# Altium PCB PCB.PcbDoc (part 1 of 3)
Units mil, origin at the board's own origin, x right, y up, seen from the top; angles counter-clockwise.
Board outline 5000 x 3500 mil, 8 copper layers (Top Layer, L2, L3, L4, L5, L6, L7, Bottom Layer), stack 46.9 mil thick; 123 components, 45 nets, 510 pads, 1300 vias.
Unrouted connection lines stored in the file: 12.
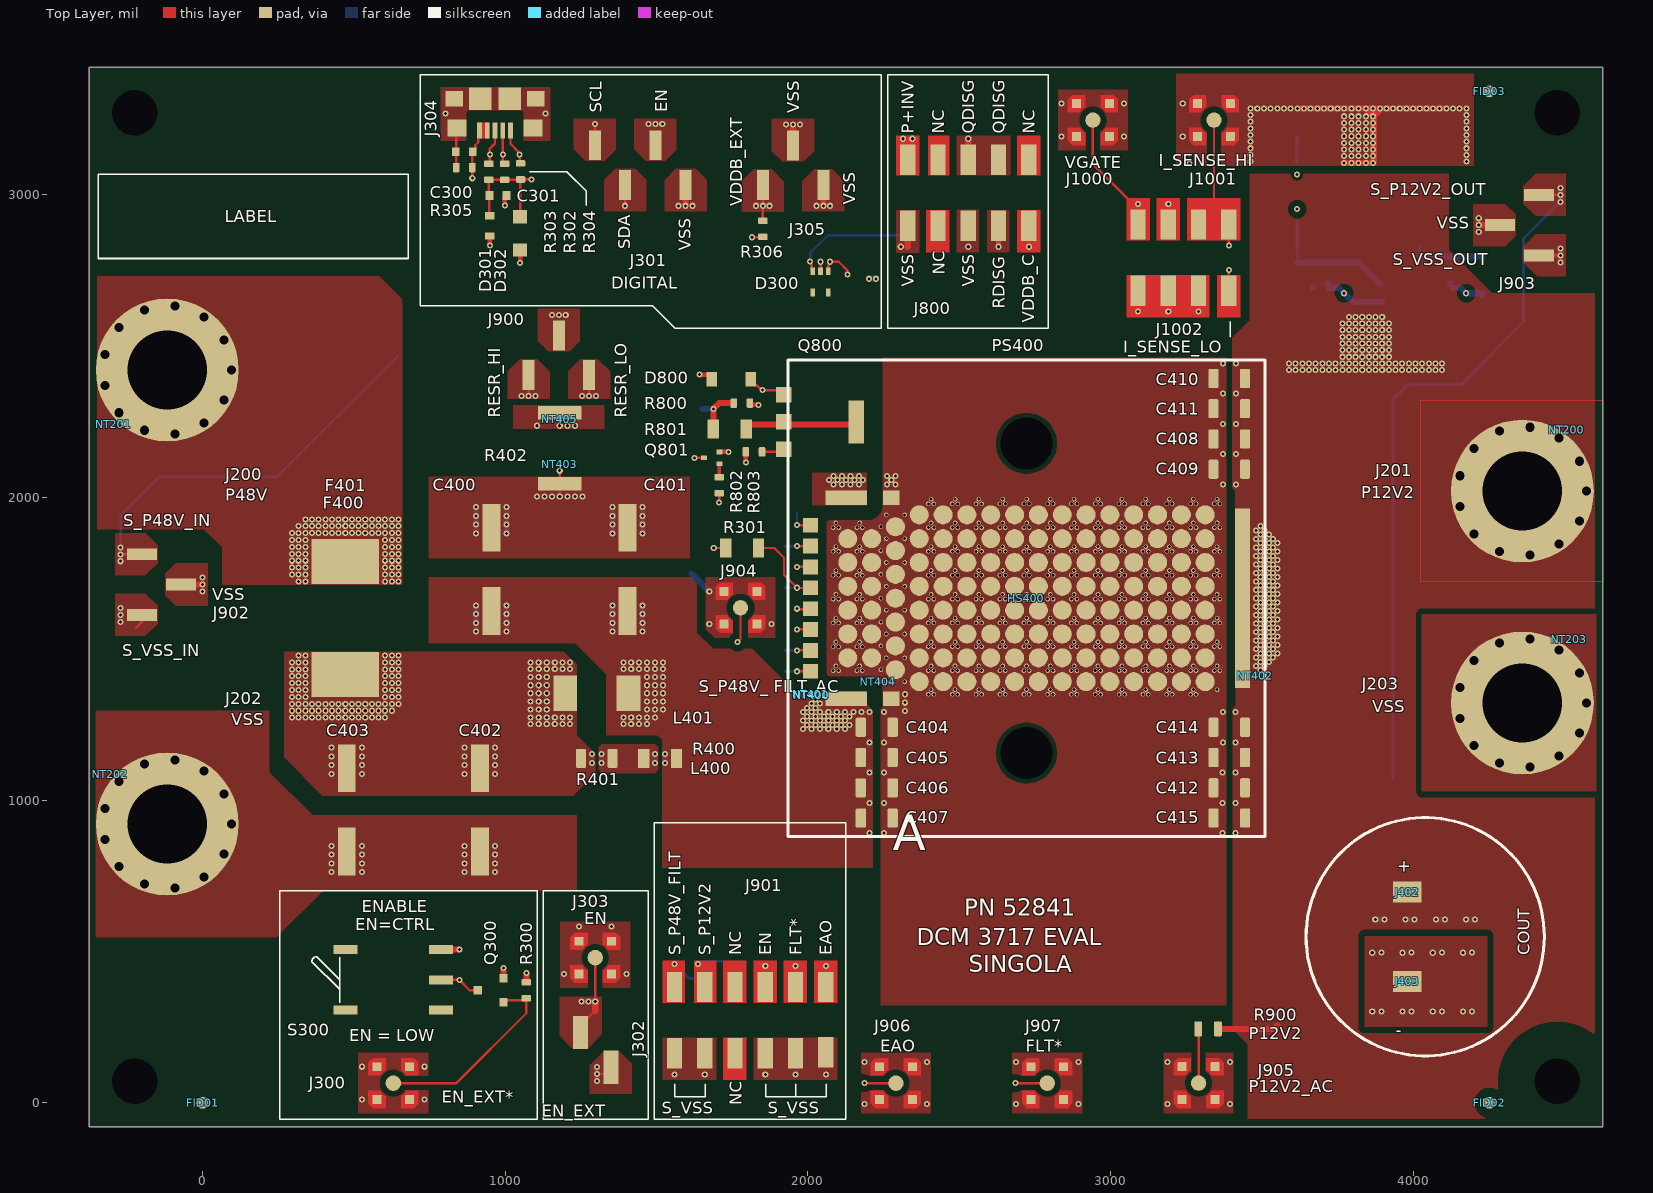
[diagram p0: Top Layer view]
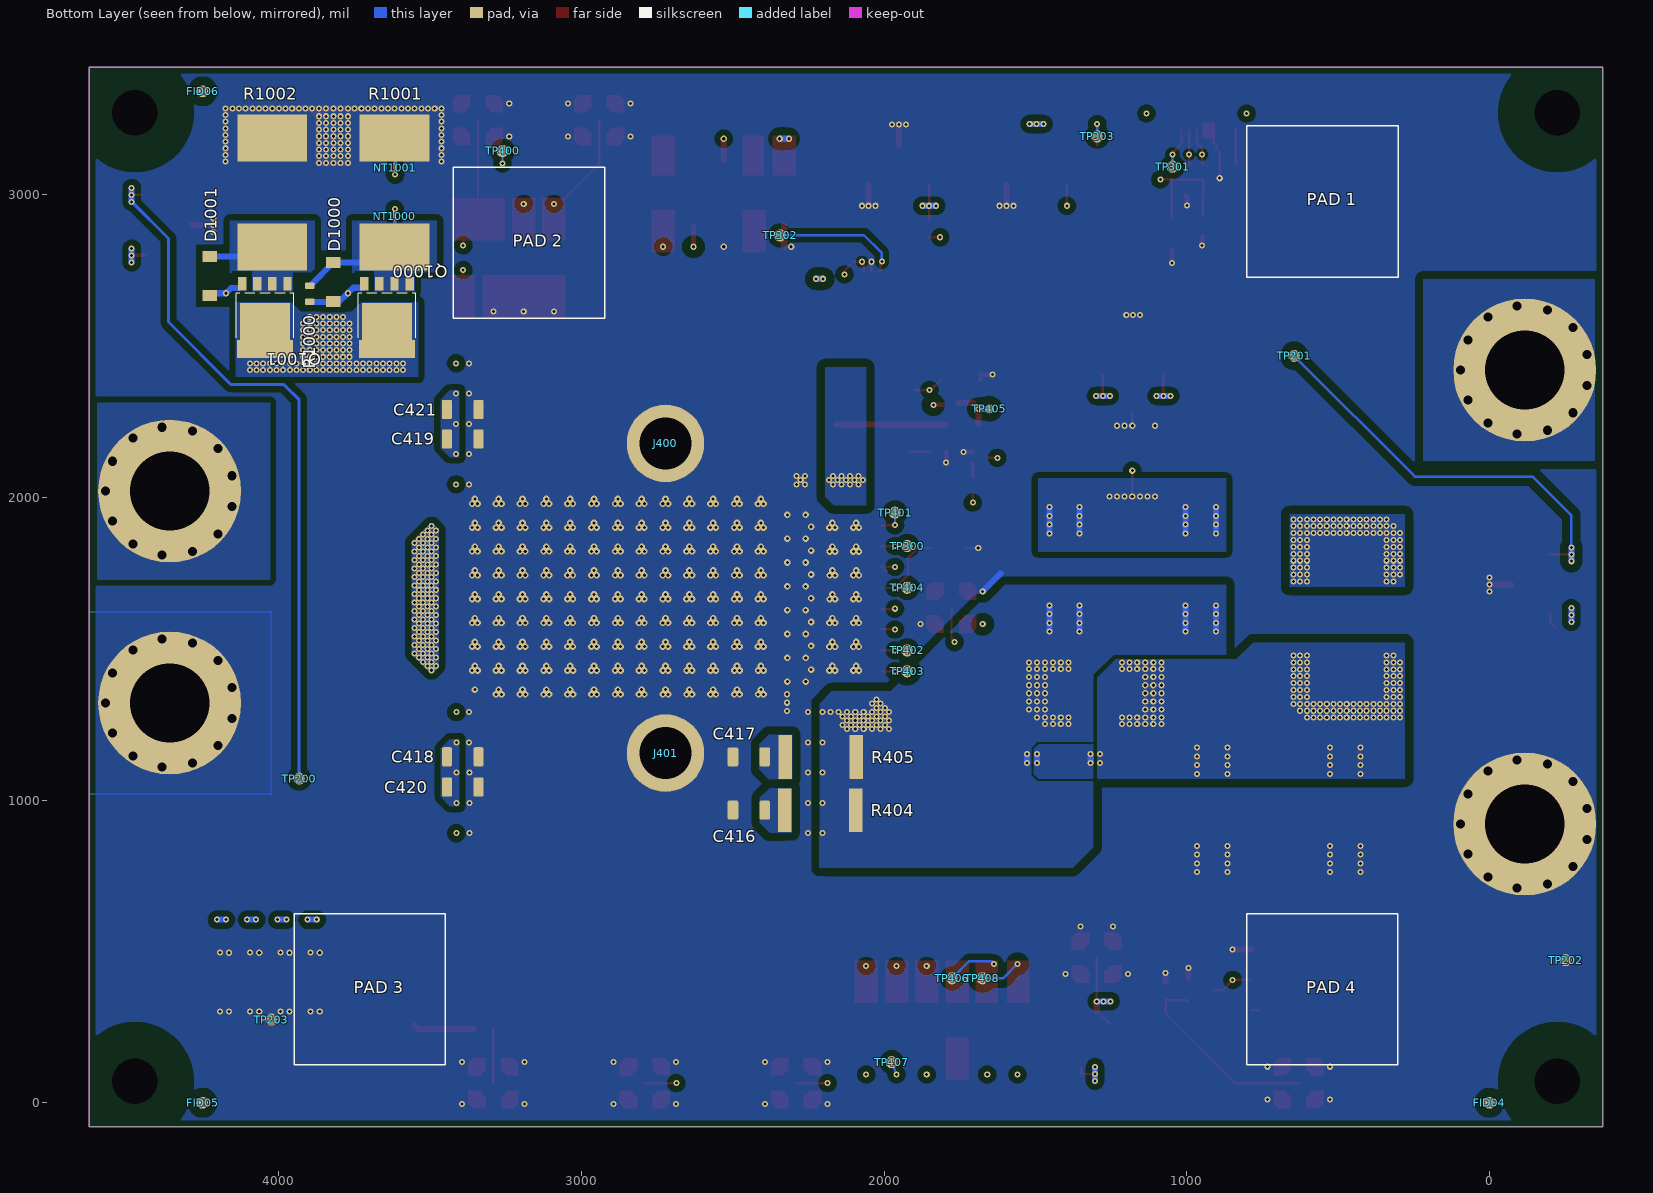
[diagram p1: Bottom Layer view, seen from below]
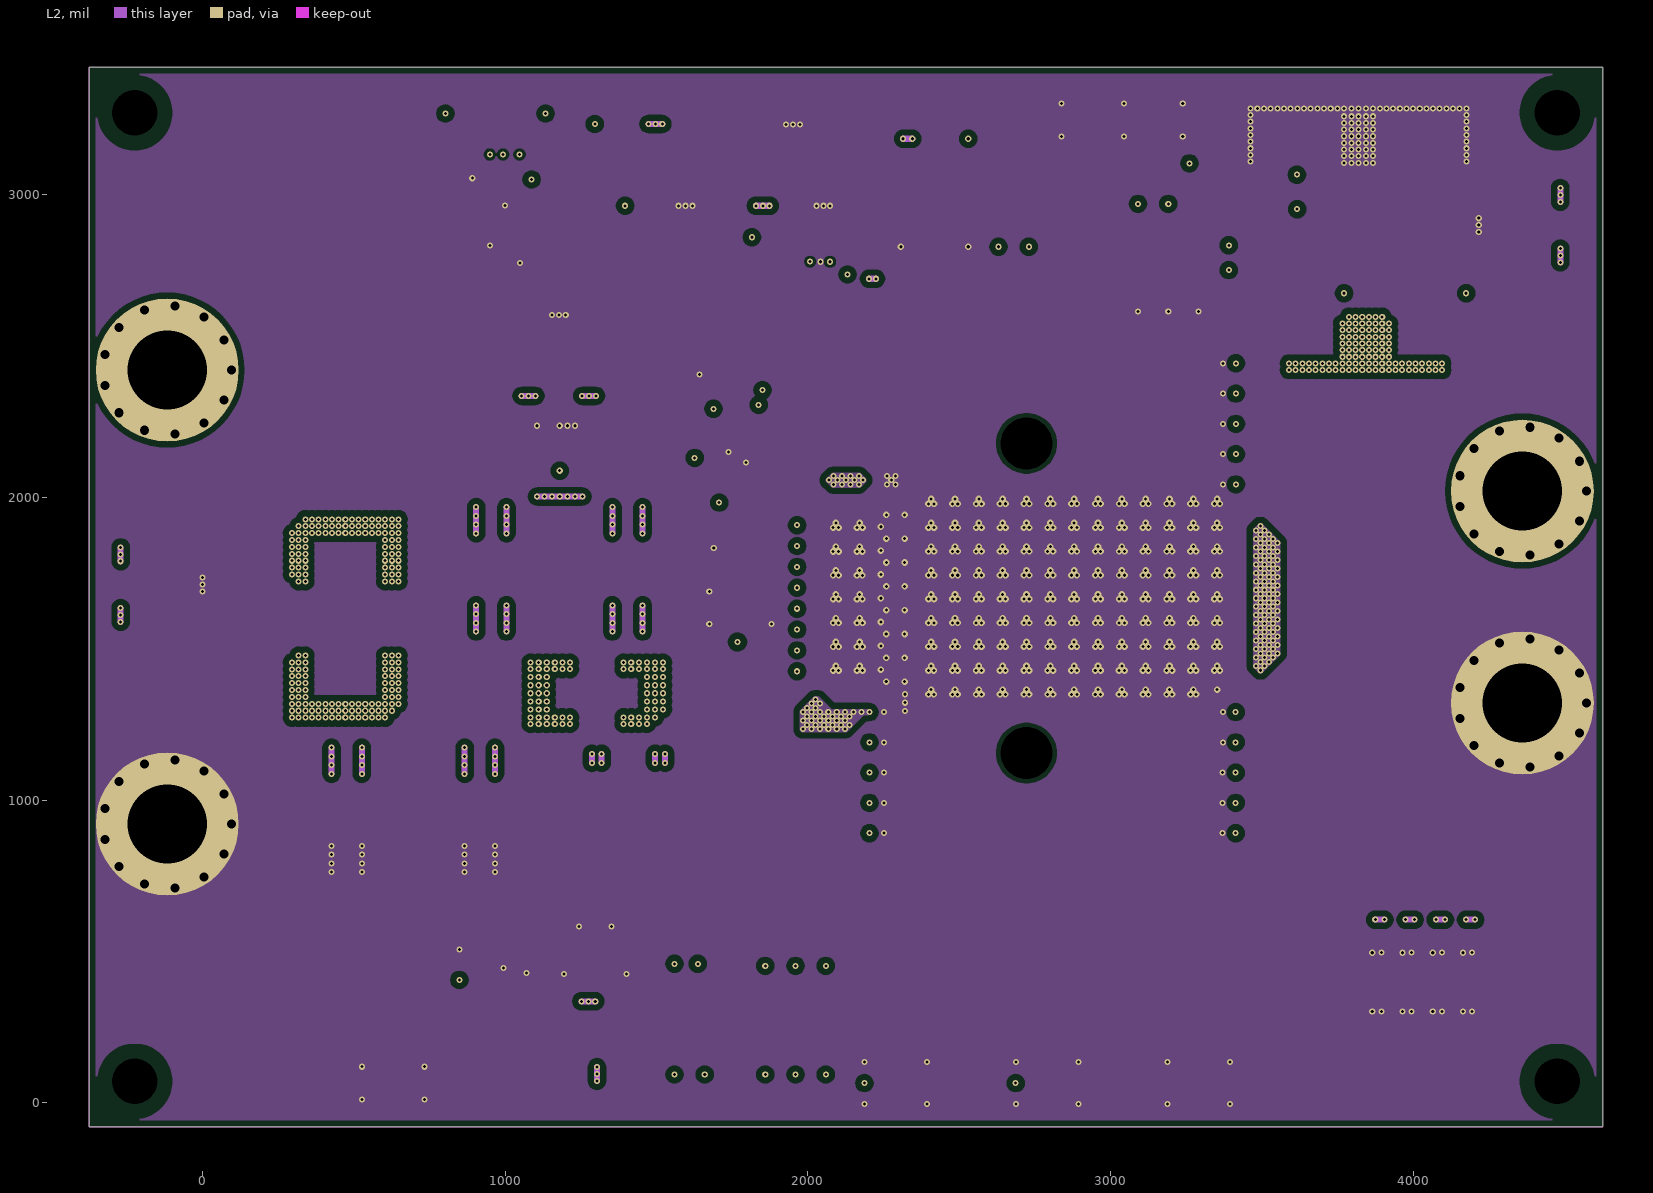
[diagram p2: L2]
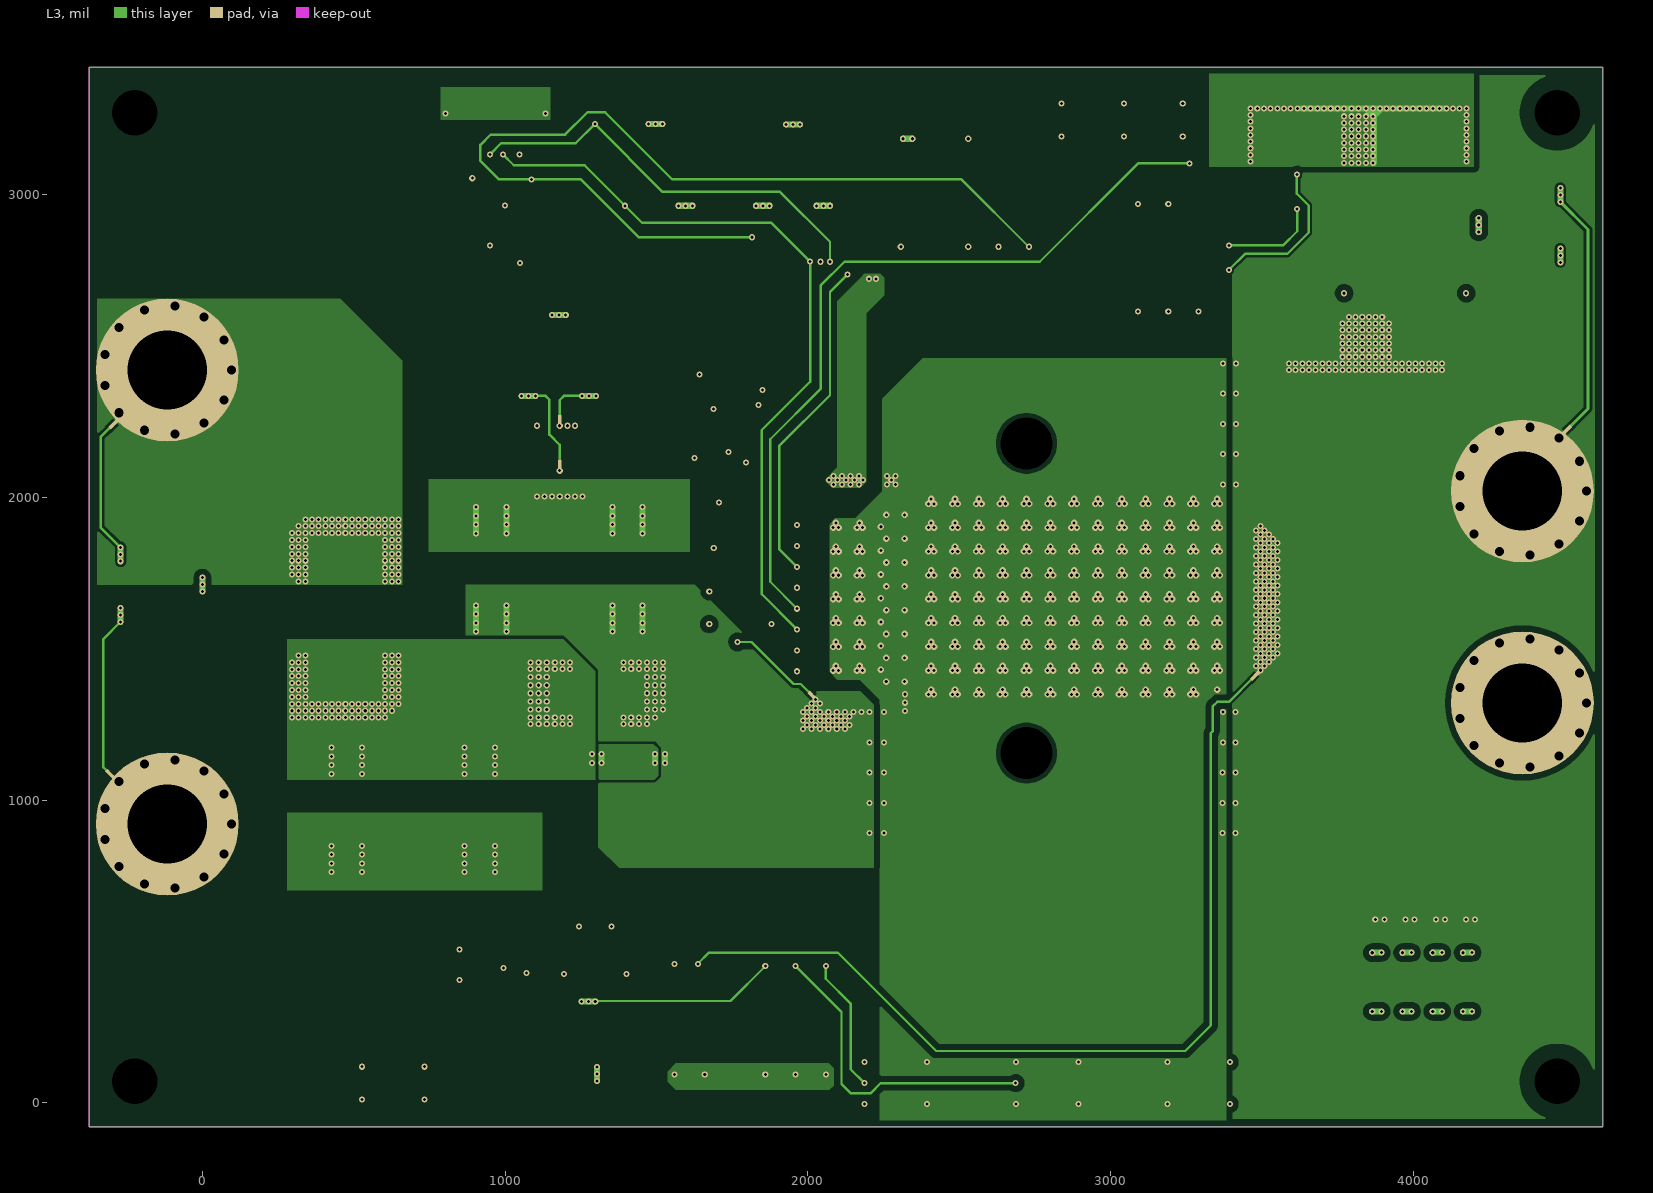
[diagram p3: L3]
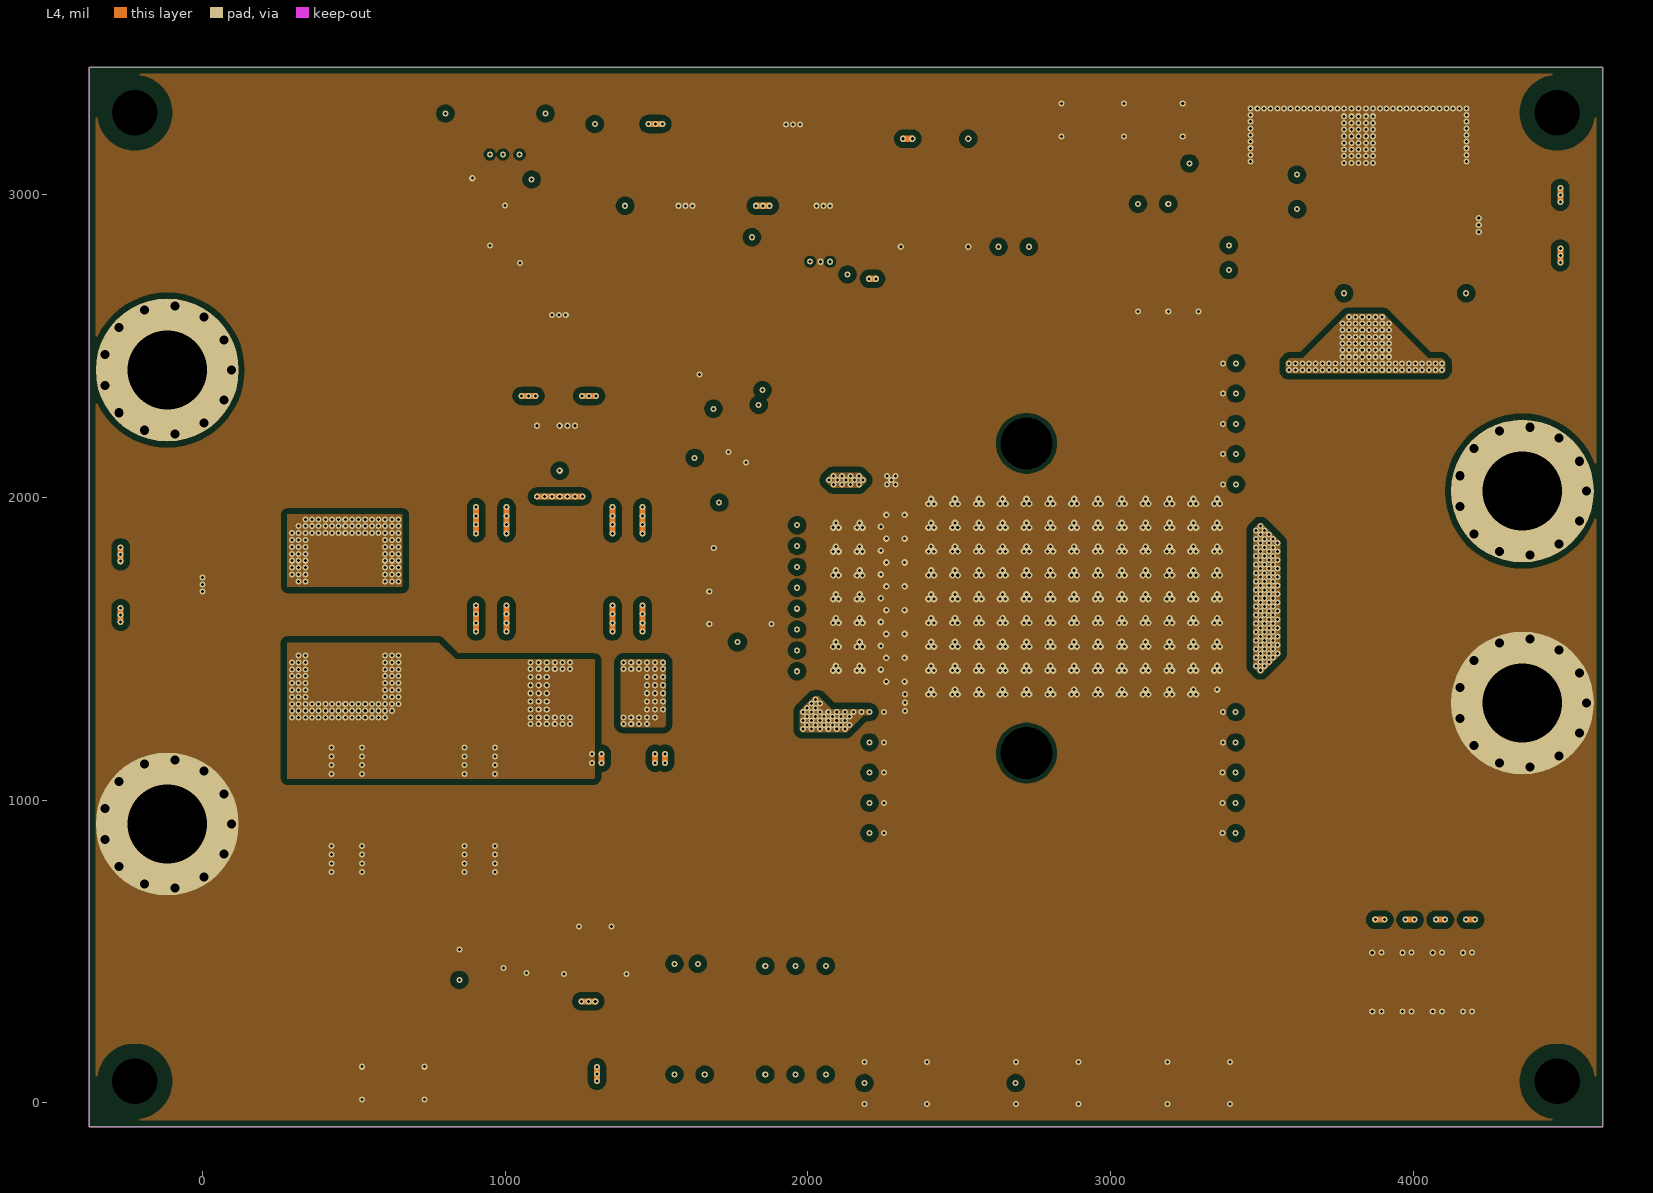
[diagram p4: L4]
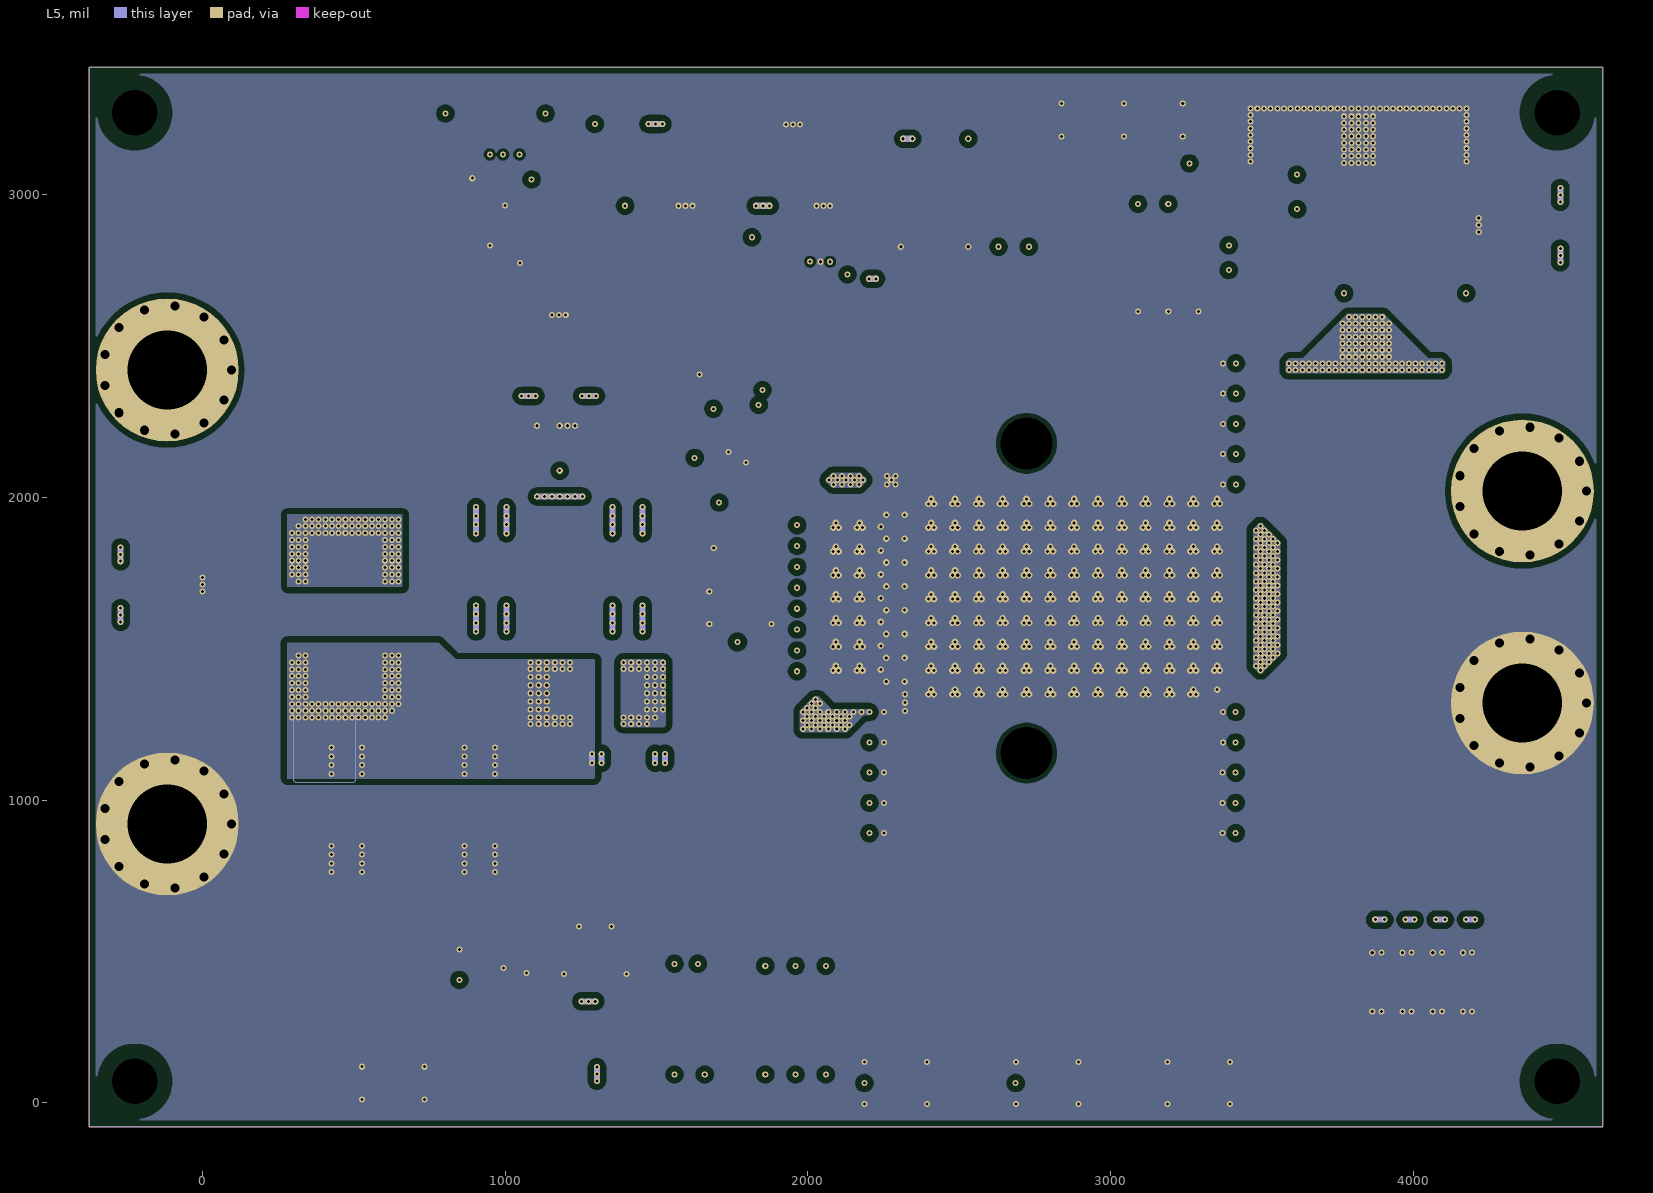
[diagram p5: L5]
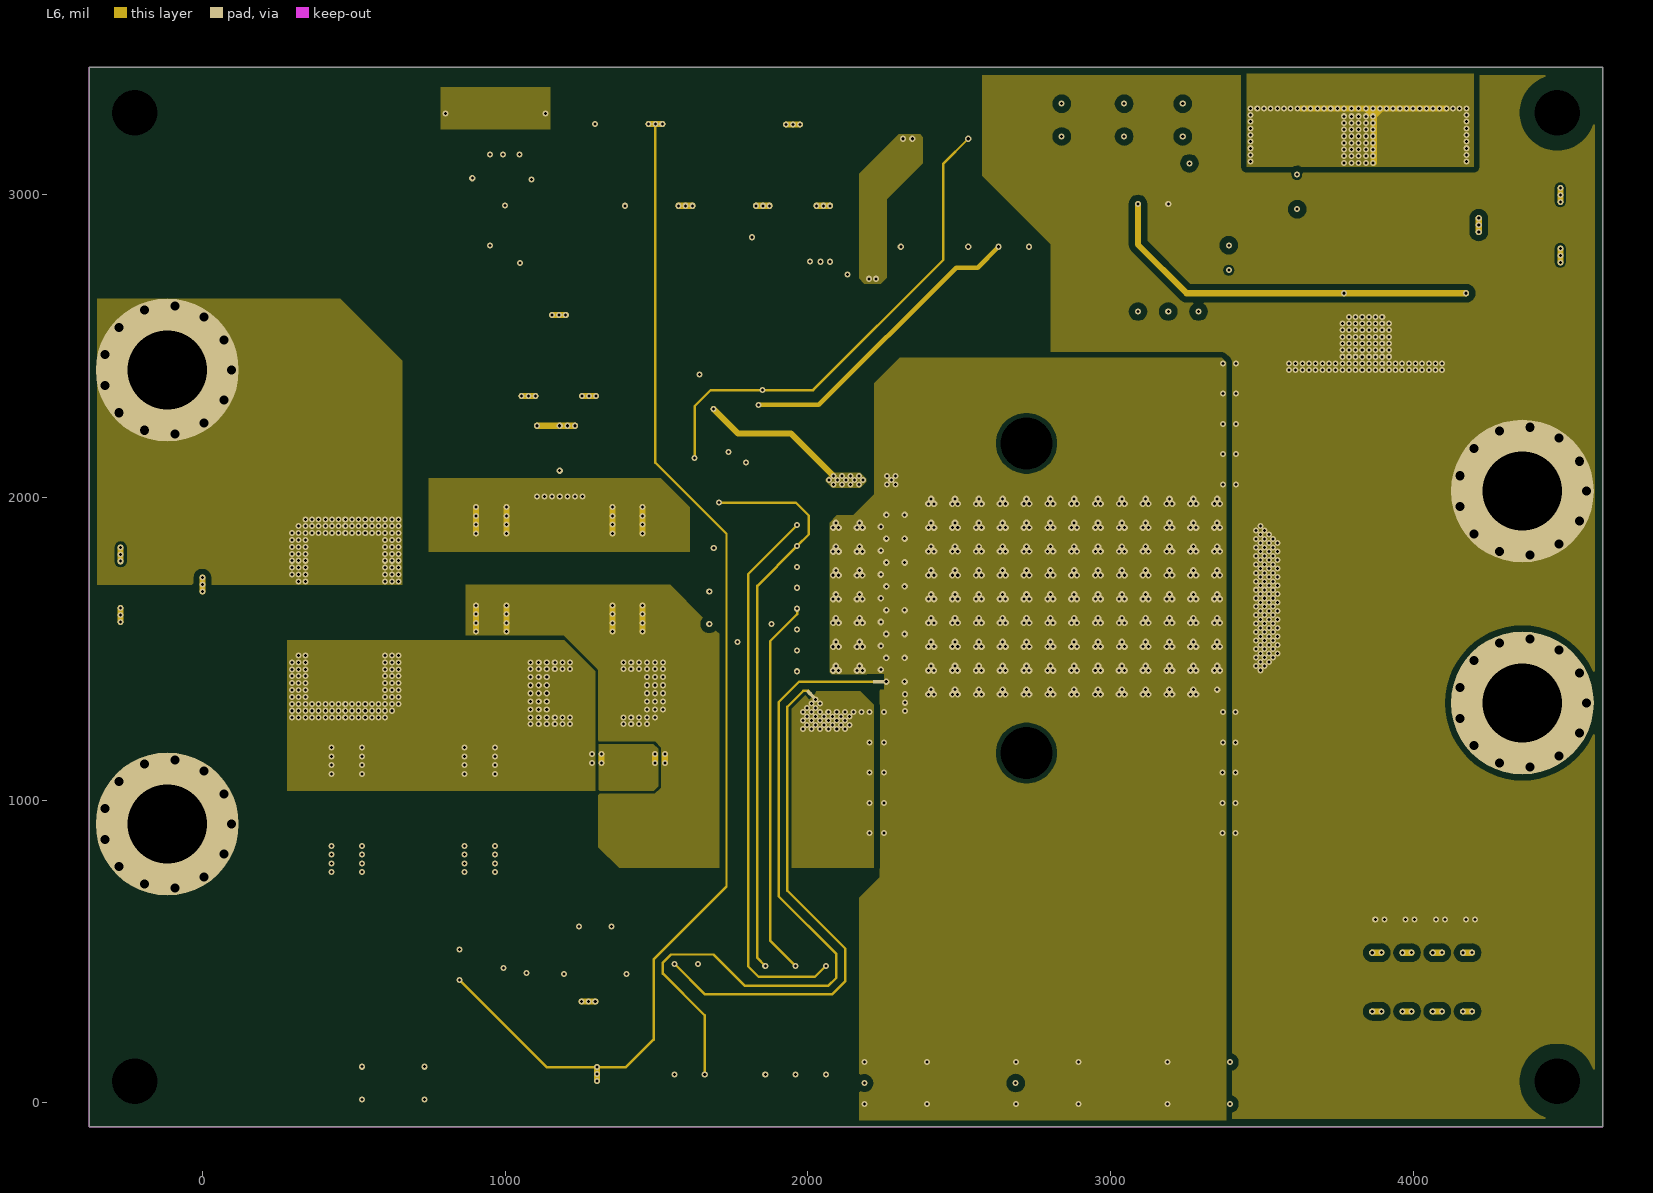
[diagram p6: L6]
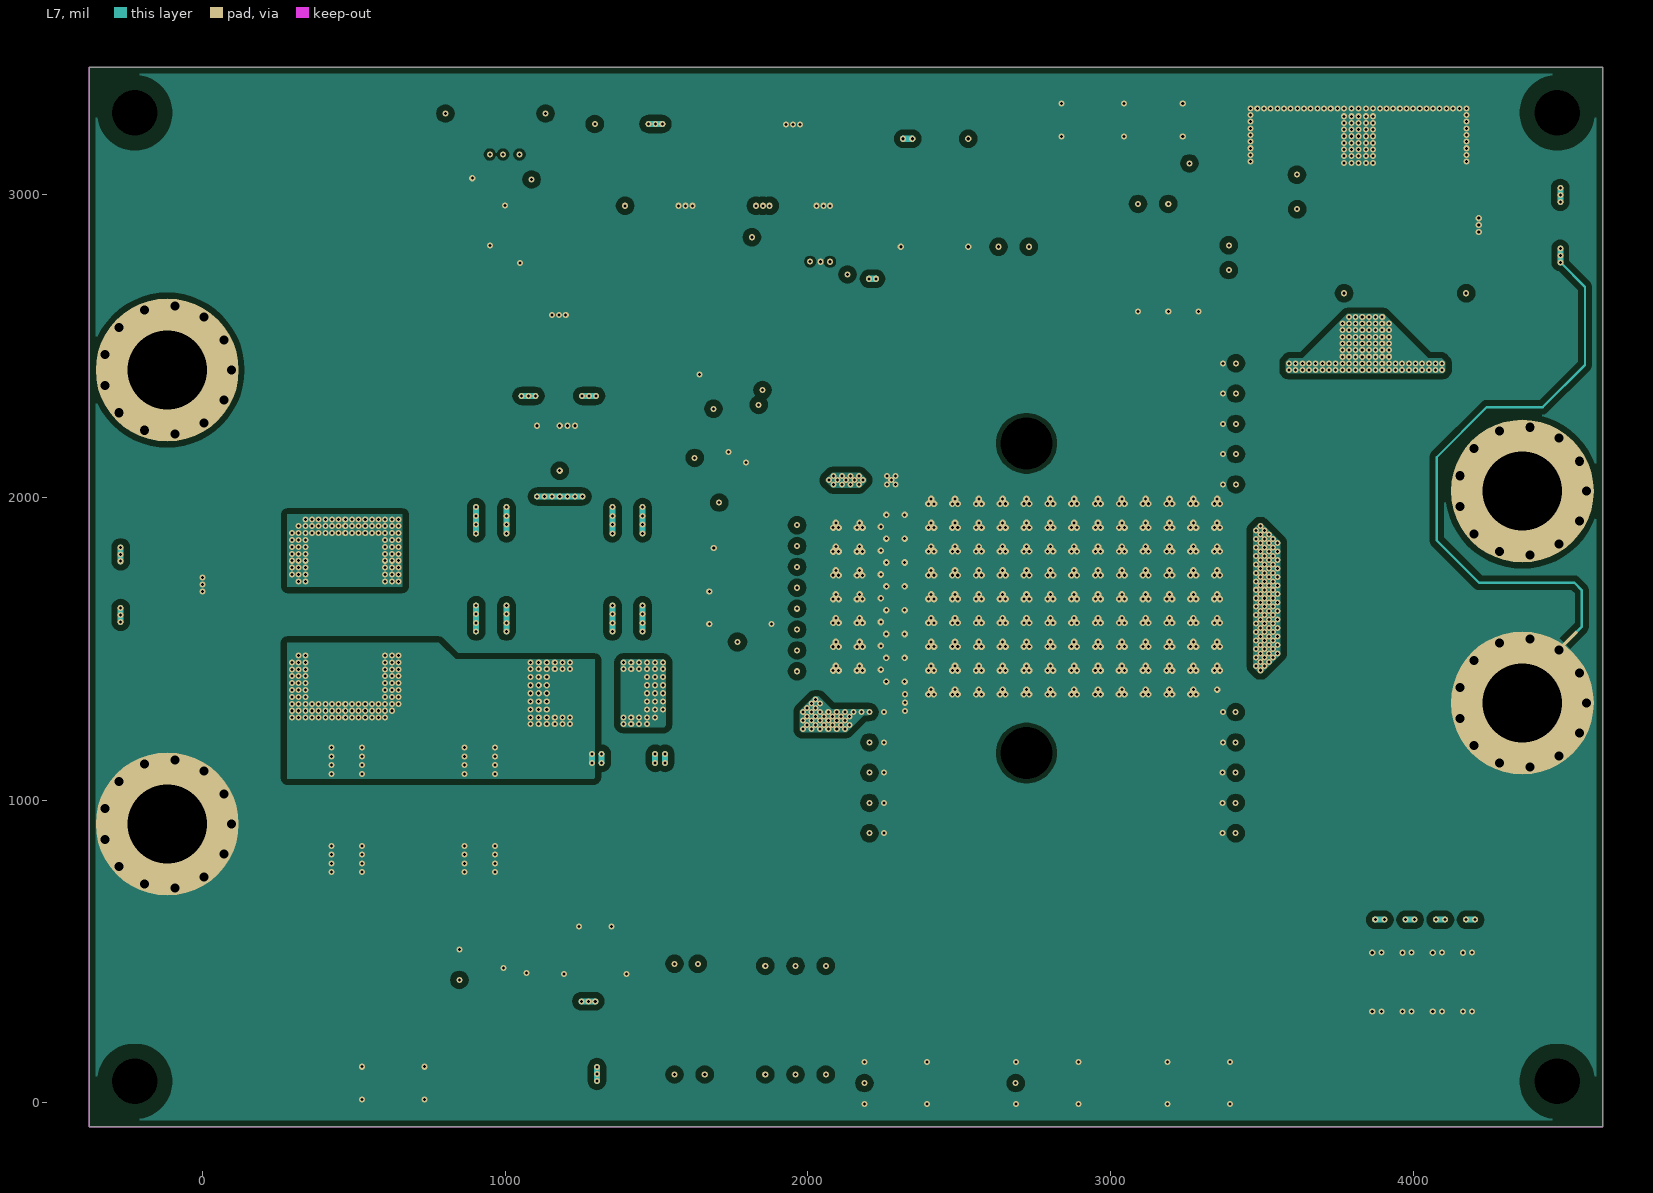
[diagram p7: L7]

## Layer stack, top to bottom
Top Solder: solder mask 0.5, Solder Resist, Dk 3.5
Top Layer: signal copper 1.8
Dielectric 1: core 4.2, FR-4, Dk 3.82
L2: signal copper 1.4
Dielectric 3: prepreg 4.2, Dk 3.66
L3: signal copper 2.2
Dielectric 4: core 3.5, Dk 3.54
L4: signal copper 2.2
Dielectric 5: prepreg 6, Dk 4.52
L5: signal copper 2.2
Dielectric 6: core 3.5, Dk 3.54
L6: signal copper 2.2
Dielectric 7: prepreg 6, Dk 5.77
L7: signal copper 2.2
Dielectric 8: core 3.5, Dk 7
Bottom Layer: signal copper 1.8
Bottom Solder: solder mask 0.5, Solder Resist, Dk 3.5

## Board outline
-374.02,-78.74 -374.02,3421.26 4625.98,3421.26 4625.98,-78.74

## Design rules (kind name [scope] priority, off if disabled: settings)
AcuteAngle AcuteAngle.1 [All] p1: minimum=8.50000000000000E+0001 checktracksonly=TRUE // Min Acute Angle
AssemblyTestPointUsage [All] p1 off:
AssemblyTestpoint [All] p1 off: testpointundercomponent=TRUE minsize=40 maxsize=100 preferedsize=60 minholesize=0 maxholesize=40 preferedholesize=32 testpointgrid=1 usegrid=TRUE gridtolerance=0.01 allowsidetop=TRUE allowsidebottom=TRUE
Clearance "Room J205" [WithinRoom('J205')] p1: gap=9.8 ignorepadtopadclearanceinfootprint=FALSE except(0: Arc-Hole Track-Hole SMDPad-Hole THPad-Hole Via-Hole Fill-Hole Poly-Hole Region-Hole Text-Hole)
Clearance "J701 Room" [WithinRoom('J701')] p2: gap=21.5 ignorepadtopadclearanceinfootprint=FALSE
Clearance "Room D200" [WithinRoom('D200')] p3: gap=9.5 ignorepadtopadclearanceinfootprint=FALSE except(0: Arc-Hole Track-Hole SMDPad-Hole THPad-Hole Via-Hole Fill-Hole Poly-Hole Region-Hole Text-Hole)
Clearance "48 to ALL" [InNetClass('48')   and InLayerClass('OUT') vs All   and InLayerClass('OUT')and not InNetClass('48')] p4: gap=27.56 ignorepadtopadclearanceinfootprint=TRUE
Clearance "Digital to ALL" [InNetClass('Digital')] p5: gap=20 ignorepadtopadclearanceinfootprint=TRUE except(0: Arc-Hole Track-Hole SMDPad-Hole THPad-Hole Via-Hole Fill-Hole Poly-Hole Region-Hole Text-Hole)
Clearance Clearance_1 [InNetClass('12')  and InLayerClass('OUT') vs All  and InLayerClass('OUT')] p6: gap=10 ignorepadtopadclearanceinfootprint=TRUE
Clearance "48 to All Inner layers" [InNetClass('48')   and InLayerClass('IN') vs All       and InLayerClass('IN')] p7: gap=9.84 ignorepadtopadclearanceinfootprint=TRUE
Clearance "VIa to Pad" [IsVia vs ispad] p8: gap=8 ignorepadtopadclearanceinfootprint=TRUE except(0: Arc-Hole Track-Hole SMDPad-Hole THPad-Hole Via-Hole Fill-Hole Poly-Hole Region-Hole Text-Hole)
Clearance "sCOPE jACK" [ISPAD AND InComponentClass('SCOPE') vs ISPAD AND InComponentClass('SCOPE')] p9: gap=11 ignorepadtopadclearanceinfootprint=FALSE except(0: Arc-Hole Track-Hole SMDPad-Hole THPad-Hole Via-Hole Fill-Hole Poly-Hole Region-Hole Text-Hole)
Clearance "KEEPOUT LAYER" [IsKeepOut and (OnLayer('Keep-Out Layer')) vs All and Not (OnLayer('Keep-Out Layer')or IsBoardCutoutRegion or InPadClass('GND pads')or InComponentClass('ZERO'))] p10: gap=25 ignorepadtopadclearanceinfootprint=FALSE except(0: Arc-Hole Track-Hole SMDPad-Hole THPad-Hole Via-Hole Fill-Hole Poly-Hole Region-Hole Text-Hole)
Clearance "Keepout and on Top" [IsKeepOut and OnTopLayer] p11: gap=0.12 ignorepadtopadclearanceinfootprint=FALSE except(0: Arc-Hole Track-Hole SMDPad-Hole THPad-Hole Via-Hole Fill-Hole Poly-Hole Region-Hole Text-Hole)
Clearance "pad to pad" [IsPad    and not InComponentClass('Lugs') vs IsPad    and not InComponentClass('Lugs')] p12: gap=7.75 ignorepadtopadclearanceinfootprint=TRUE except(0: Arc-Hole Track-Hole SMDPad-Hole THPad-Hole Via-Hole Fill-Hole Poly-Hole Region-Hole Text-Hole)
Clearance [All] p13: gap=8 ignorepadtopadclearanceinfootprint=FALSE except(0: Arc-Hole Track-Hole SMDPad-Hole THPad-Hole Via-Hole Fill-Hole Poly-Hole Region-Hole Text-Hole)
ComponentClearance [HasFootprint('TP_030_RND_SMD') vs HasFootprint('TP_030_RND_SMD')] p1: gap=50 collisioncheckmode=3 verticalgap=0 showdistances=FALSE
ComponentClearance "NET TIE" [HasFootprint('NET TIE')] p2: gap=0 collisioncheckmode=3 verticalgap=0 showdistances=FALSE
ComponentClearance "ZERO TO ALL" [(InComponentClass('ZERO'))] p3: gap=0 collisioncheckmode=3 verticalgap=0 showdistances=FALSE
ComponentClearance "Board Outline to Body Clearance" [(OnLayer('Board Outline Check') AND IsComponentBody) vs NOT (InComponentClass('FIDUCIALS') or OnLayer('Board Outline Check'))] p4: gap=19.68 collisioncheckmode=3 verticalgap=0 showdistances=FALSE // ComponentClearance.4
ComponentClearance "MLP to Body Clerance" [(InComponentClass('MLP'))] p5: gap=14.76 collisioncheckmode=3 verticalgap=0 showdistances=FALSE // ComponentClearance.5
ComponentClearance "BGA to Body Clerance" [(InComponentClass('BGA'))] p6: gap=14.76 collisioncheckmode=3 verticalgap=0 showdistances=TRUE // ComponentClearance.5
ComponentClearance "Body to Body Clerance (Default)" [All vs All     and not InComponent('HS100')] p7: gap=9.8 collisioncheckmode=3 verticalgap=0 showdistances=TRUE // ComponentClearance.1
DiffPairsRouting RoutingDiffPairsRouting.1 [All] p1 off: maxlimit=10 minlimit=10 mostfreqgap=10 toplayer_minwidth=15 toplayer_maxwidth=15 toplayer_prefwidth=15 midlayer1_minwidth=15 midlayer1_maxwidth=15 midlayer1_prefwidth=15 midlayer2_minwidth=15 midlayer2_maxwidth=15 midlayer2_prefwidth=15 midlayer3_minwidth=15 midlayer3_maxwidth=15 midlayer3_prefwidth=15 midlayer4_minwidth=15 midlayer4_maxwidth=15 midlayer4_prefwidth=15 midlayer5_minwidth=15 midlayer5_maxwidth=15 midlayer5_prefwidth=15 midlayer6_minwidth=15 midlayer6_maxwidth=15 midlayer6_prefwidth=15 bottomlayer_minwidth=15 bottomlayer_maxwidth=15 bottomlayer_prefwidth=15 maxuncoupledlength=500 // DiffPairsRouting
FabricationTestPointUsage TestPointUsage [All] p1 off: valid=0 allowmultiple=FALSE
FabricationTestpoint Testpoint [All] p1 off: side=3 testpointundercomponent=TRUE minsize=40 maxsize=100 preferedsize=60 minholesize=0 maxholesize=40 preferedholesize=32 testpointgrid=1 allowsidetop=TRUE allowsidebottom=TRUE usegrid=TRUE gridtolerance=0.01
FanoutControl RoutingFanout_BGA.1 [IsBGA] p1 off: bgadir=Out bgaviamode=Centered fanoutstyle=Auto fanoutdirection=Alternating viagrid=1 // Fanout_BGA (Default Rule)
FanoutControl RoutingFanout_LCC.1 [IsLCC] p2 off: bgadir=Out bgaviamode=Centered fanoutstyle=Auto fanoutdirection=Alternating viagrid=1 // Fanout_LCC (Default Rule)
FanoutControl RoutingFanout_SOIC.1 [IsSOIC] p3 off: bgadir=Out bgaviamode=Centered fanoutstyle=Auto fanoutdirection=Alternating viagrid=1 // Fanout_SOIC (Default Rule)
FanoutControl RoutingFanout_Small.1 [(CompPinCount < 5)] p4 off: bgadir=Out bgaviamode=Centered fanoutstyle=Auto fanoutdirection=Alternating viagrid=1 // Fanout_Small (Default Rule)
HoleSize HoleSize.1 [((StartLayer = 'L2') and (StopLayer = 'L13'))  or ((StartLayer = 'L2') and (StopLayer = 'L9'))] p1: absolutevalues=TRUE maxlimit=98.43 minlimit=7.87 maxpercent=80.000 minpercent=20.000 // VIA29.01, VIA213.01
HoleSize HoleSize.2 [((StartLayer = 'L2') and (StopLayer = 'L3'))or ((StartLayer = 'L12') and (StopLayer = 'L13'))] p2: absolutevalues=TRUE maxlimit=98.43 minlimit=4.5 maxpercent=80.000 minpercent=20.000 // VIA23.01, VIA1213.01
HoleSize HoleSize.3 [((StartLayer = 'Top') and (StopLayer = 'L2'))  or ((StartLayer = 'L13') and (StopLayer = 'Bottom')) or ((StartLayer = 'L9') and (StopLayer = 'Bottom'))] p3: absolutevalues=TRUE maxlimit=98.43 minlimit=4.5 maxpercent=80.000 minpercent=20.000 // VIA12.01, VIA1314.01
HoleToHoleClearance HoleToHole.1 [((StartLayer = 'L2') and (StopLayer = 'L13')) or ((StartLayer = 'L2') and (StopLayer = 'L9')) vs ((StartLayer = 'Top') and (StopLayer = 'L2'))  or ((StartLayer = 'L13') and (StopLayer = 'Bottom')) or ((StartLayer = 'L9') and (StopLayer = 'Bottom'))] p1: gap=7.87 allowstackedmicrovias=TRUE // L2/13 to Outer
HoleToHoleClearance HoleToHole.3 [((StartLayer = 'Top') and (StopLayer = 'L2'))  or ((StartLayer = 'L13') and (StopLayer = 'Bottom')) or ((StartLayer = 'L9') and (StopLayer = 'Bottom')) vs ((StartLayer = 'Top') and (StopLayer = 'L2'))  or ((StartLayer = 'L13') and (StopLayer = 'Bottom')) or ((StartLayer = 'L9') and (StopLayer = 'Bottom'))] p2: gap=4.92 allowstackedmicrovias=FALSE // VIA12.02, VIA1314.02
HoleToHoleClearance HoleToHole.4 [((StartLayer = 'Top') and (StopLayer = 'L2'))   or     ((StartLayer = 'L13') and (StopLayer = 'Bottom')) vs ((StartLayer = 'L2') and (StopLayer = 'L3'))   or ((StartLayer = 'L12') and (StopLayer = 'L13'))] p3: gap=7.87 allowstackedmicrovias=TRUE
HoleToHoleClearance HoleToHole.5 [((StartLayer = 'L2') and (StopLayer = 'L3'))  or ((StartLayer = 'L12') and (StopLayer = 'L13')) vs ((StartLayer = 'L2') and (StopLayer = 'L3'))  or ((StartLayer = 'L12') and (StopLayer = 'L13'))] p4: gap=4.92 allowstackedmicrovias=FALSE // VIA23.02, VIA1213.02
HoleToHoleClearance HoleToHole.6 [((StartLayer = 'L2') and (StopLayer = 'L13')) or ((StartLayer = 'L2') and (StopLayer = 'L9')) vs ((StartLayer = 'L2') and (StopLayer = 'L3'))or ((StartLayer = 'L12') and (StopLayer = 'L13'))] p5: gap=4.92 allowstackedmicrovias=FALSE // L2/13 to +/- N1
HoleToHoleClearance HoleToHole.7 [((StartLayer = 'L2') and (StopLayer = 'L13'))  or ((StartLayer = 'L2') and (StopLayer = 'L9')) vs ((StartLayer = 'L2') and (StopLayer = 'L13')) or ((StartLayer = 'L2') and (StopLayer = 'L9'))] p6: gap=8 allowstackedmicrovias=FALSE // VIA29.02, VIA213.02
MinimumAnnularRing MinAnnRing.3 [((StartLayer = 'L2') and (StopLayer = 'L3')) or ((StartLayer = 'L12') and (StopLayer = 'L13'))] p1: minimumring=2.95 // ILX.03
MinimumAnnularRing MinAnnRing.1 [((StartLayer = 'Top') and (StopLayer = 'L2'))  or ((StartLayer = 'L13') and (StopLayer = 'Bottom')) or ((StartLayer = 'L9') and (StopLayer = 'Bottom'))] p2: minimumring=3.66 // TL1.03, BL10.03, BL14.03
MinimumAnnularRing MinAnnRing.2 [((StartLayer = 'L2') and (StopLayer = 'L13'))  or ((StartLayer = 'L2') and (StopLayer = 'L9'))] p3: minimumring=5.41 // ILX.04
MinimumSolderMaskSliver [All] p1: minsoldermaskwidth=3.94
MinimumSolderMaskSliver SilkscreenOverComponentPads [All] p2 off: minsoldermaskwidth=10 // NOT USED SilkscreenOverComponentPads
PasteMaskExpansion PM.01 [All] p1: expansion=0 // PasteMaskExpansion
PlaneClearance "NOT USED POWER PLANE" [All] p1 off: clearance=20
PlaneConnect "NOT USED POWER PLANE CONNECT" [All] p1 off: planeconnectstyle=Relief reliefexpansion=20 reliefentries=4 reliefconductorwidth=10 reliefairgap=10
PolygonConnect [InPadClass('Thermal')] p1: connectstyle=Relief reliefconductorwidth=8 reliefentries=4 polygonreliefangle="45 Angle" airgapwidth=5.5
PolygonConnect PLANE.4 [All] p2: connectstyle=Direct reliefconductorwidth=10 reliefentries=4 polygonreliefangle="90 Angle" airgapwidth=10 // PolygonConnect
RoomDefinition J701 [False] p1: confinementstyle=ConfineIn formatcopy=TRUE lockcomponents=FALSE outline 1721.85,1690.37 1885.41,1690.37 1885.41,1500.23 1721.85,1500.23
RoomDefinition D200 [False] p2: confinementstyle=ConfineIn formatcopy=TRUE lockcomponents=FALSE outline 1993.2,2789.09 2093.23,2789.09 2093.23,2729.55 1993.2,2729.55
RoomDefinition J205 [False] p3: confinementstyle=ConfineIn formatcopy=TRUE lockcomponents=FALSE outline 938.98,3245.91 1057.51,3245.91 1057.51,3132.61 938.98,3132.61
RoutingCorners RoutingRoutingCorners.1 [All] p1: cornerstyle=45-Degree minsetback=100 maxsetback=100 // RoutingCorners
RoutingPriority RoutingPriority.1 [All] p1 off: routingpriority=0 // Routing Priority Default
RoutingTopology RoutingTopology.1 [All] p1: topology=Shortest // Routing Topology Default
RoutingVias RoutingRoutingVias.1 [All] p1: holewidth=9.84 width=19.68 viastyle="Through Hole" minholewidth=4.43 minwidth=11.81 maxholewidth=20 maxwidth=30 // Routing Vias Default
SilkToSilkClearance SilkToSilkClearance.1 [All] p1 off: silktosilkclearance=4.92 // OT USED SilkToSilkClearance
SolderMaskExpansion SM.01 [All] p1: expansion=1.97 istentingtop=FALSE // Solder Mask Expansion - TSM.01, BSM01
Width Width_1 [All] p1: maxlimit=50 minlimit=8 preferedwidth=8
9 further rules are at their usual default settings.

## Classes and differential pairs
net class 12: P12V2 P12V2_AC S_P12V2 S_P12V2_OUT
component class ZERO: F400 J200 L400
net class 48: NetC416_1 NetC417_1 NetL400_1 P48V P48V_FILT P48V_FUSED P+INV RDISG S_P48V_FILT S_P48V_IN
net class Digital: ADDR EAO EN EN_EXT EN_EXT* FLT* I_SENSE_HI NetPS400_12 NetPS400_13 NetQ801_B QDISD QDISG QDISS SCL SDA USB_SHELL VDDB_CLAMPED VDDB_EXT VDDB_USB VGATE VSOURCE1 VSOURCE2 VSS

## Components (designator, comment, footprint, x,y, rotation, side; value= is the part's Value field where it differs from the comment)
C300 "0603" 0603-C_L 864.5,3142.72 r0 top
C301 "0603" 0603-C_L 975.72,2998.88 r0 top
C400 "CAP_ALEL" C_ALEL10X12R7 953.93,1762.71 r90 top
C401 "CAP_ALEL" C_ALEL10X12R7 1403.93,1762.71 r90 top
C402 "CAP_ALEL" C_ALEL10X12R7 916,968 r270 top
C403 "CAP_ALEL" C_ALEL10X12R7 476,968 r270 top
C404 "1206" 1206-C-GRM31CC72A475KE11 2227.44,1240.95 r0 top
C405 "1206" 1206-C-GRM31CC72A475KE11 2227.44,1140.95 r0 top
C406 "1206" 1206-C-GRM31CC72A475KE11 2227.44,1040.95 r0 top
C407 "1206" 1206-C-GRM31CC72A475KE11 2227.44,940.95 r0 top
C408 "1206" 1206-C-FLT 3392.5,2193.63 r180 top
C409 "1206" 1206-C-FLT 3392.5,2093.63 r180 top
C410 "1206" 1206-C-FLT 3392.5,2393.63 r180 top
C411 "1206" 1206-C-FLT 3392.5,2293.63 r180 top
C412 "1206" 1206-C-FLT 3392.5,1040.96 r180 top
C413 "1206" 1206-C-FLT 3392.5,1140.96 r180 top
C414 "1206" 1206-C-FLT 3392.5,1240.96 r180 top
C415 "1206" 1206-C-FLT 3392.5,940.96 r180 top
C416 "1206" 1206-C-GRM31CC72A475KE11 2447,967 r0 bottom
C417 "1206" 1206-C-GRM31CC72A475KE11 2447,1143 r0 bottom
C418 "1206" 1206-C-FLT 3392.5,1143.42 r180 bottom
C419 "1206" 1206-C-FLT 3392.5,2193.63 r180 bottom
C420 "1206" 1206-C-FLT 3392.5,1043.42 r180 bottom
C421 "1206" 1206-C-FLT 3392.5,2291.17 r180 bottom
D300 "SOT353" SOT353-D 2042.01,2712.77 r270 top
D301 "SOD523" SOD523-SDMIOU45 948.72,2897.72 r270 top
D302 "SOD123" SOD123F-NEXPERIA 1048.72,2872.72 r270 top
D800 "SOD123" SOD123_L 1746.89,2391.18 r180 top
D1000 "SOD123" SOD123-D-MMSZ4 3819.94,2712.52 r90 bottom
D1001 "SOD123" SOD123-D-MMSZ4 4228.97,2732.52 r90 bottom
F400 "FUSE" F_NANO_456-XXA-XXA 471.29,1602.02 r270 top
F401 "FUSE" F_NANO_456-XXA 471.3,1602.02 r270 top
FID01 "FIDUCIAL" FIDUCIAL-040 0,0 r90 top
FID02 "FIDUCIAL" FIDUCIAL-040 4251.97,0 r90 top
FID03 "FIDUCIAL" FIDUCIAL-040 4251.97,3342.52 r270 top
FID04 "FIDUCIAL" FIDUCIAL-040 0,0 r90 bottom
FID05 "FIDUCIAL" FIDUCIAL-040 4251.97,0 r90 bottom
FID06 "FIDUCIAL" FIDUCIAL-040 4251.97,3342.52 r90 bottom
HS400 "HEATSINK" "HEAT SINK 40x40" 2722.44,1667.32 r0 top locked
J200 "GENERIC_PART" "RADSERT-10-737-491-001 MASK PLUGGED" -117.02,2421.26 r0 top
J201 "GENERIC_PART" "RADSERT-10-737-491-001 MASK PLUGGED" 4360.98,2021.26 r0 top
J202 "GENERIC_PART" "RADSERT-10-737-491-001 MASK PLUGGED" -117.02,921.26 r0 top
J203 "GENERIC_PART" "RADSERT-10-737-491-001 MASK PLUGGED" 4360.98,1321.26 r0 top
J300 "JACK_VERTICAL" "SCOPE JACK" 630,65 r90 top
J301 "CN4_HARWIN_M20877XXXX" CN4_HARWIN-M20877XXXX 1446.13,3098.86 r180 top
J302 "CN2_HARWIN_M20" CN2_HARWIN-M20877XXXX 1299,175 r180 top
J303 "JACK_VERTICAL" "SCOPE JACK" 1297.35,479.57 r0 top
J304 "CN6_TE_2174507" CN6_TE-2174507 966.13,3265.53 r180 top
J305 "CN3_HARWIN_M20" CN3_HARWIN-M20#1 1951.13,3097.91 r180 top
J400 "PEM" "KFS2-M3 4.22"#1 2722.47,2179.08 r180 bottom
J401 "PEM" "KFS2-M3 4.22"#2 2722.44,1155.51 r180 bottom
J402 "PIN_RECPT" CN1_MILLMAX_SM_RECEPTACLE 3980.98,696.31 r0 top
J403 "PIN_RECPT" CN1_MILLMAX_SM_RECEPTACLE 3980.98,401.03 r0 top
J800 "CN10_DIGIKEY_95278" CN10_DIGIKEY_95278 2529.98,3007.26 r90 top
J900 "CN3_HARWIN_M20" CN3_HARWIN-M20#2 1177,2470 r180 top
J901 "CN12_DIGIKEY_95278" CN12_DIGIKEY_95278 1809.21,272.83 r270 top
J902 "CN3_HARWIN_M20" CN3_HARWIN-M20#1 -136.21,1712.6 r90 top
J903 "CN3_HARWIN_M20" CN3_HARWIN-M20#1 4352.14,2900.26 r270 top
J904 "JACK_VERTICAL" "SCOPE JACK" 1777.3,1635.91 r0 top
J905 "JACK_VERTICAL" "SCOPE JACK" 3291.1,65.11 r90 top locked
J906 "JACK_VERTICAL" "SCOPE JACK" 2290.98,65 r0 top
J907 "JACK_VERTICAL" "SCOPE JACK" 2790.98,65 r0 top
J1000 "JACK_VERTICAL" "SCOPE JACK" 2941.97,3247.52 r0 top
J1001 "JACK_VERTICAL" "SCOPE JACK" 3341.97,3247.52 r0 top
J1002 "CN8_DIGIKEY_95278" CN8_DIGIKEY_95278 3240.97,2792.52 r270 top
L400 "1206" 1206-L_BLM31P 1512,1138.3 r0 top
L401 "2727" 2727 1302.44,1353.3 r0 top
NT200 "Net_Tie" "NET TIE"#1 4507.97,2223.4 r225 top net-tie
NT201 "Net_Tie" "NET TIE"#1 -294,2243 r45 top net-tie
NT202 "Net_Tie" "NET TIE"#1 -305,1086 r315 top net-tie
NT203 "Net_Tie" "NET TIE"#2 4517.97,1533.4 r45 top net-tie
NT400 "Net_Tie" "NET TIE"#3 2012.69,1347.53 r135 top net-tie
NT401 "Net_Tie" "NET TIE"#4 2009.82,1349.81 r315 top net-tie
NT402 "Net_Tie" "NET TIE"#1 3477.87,1410.99 r45 top net-tie
NT403 "Net_Tie" "NET TIE"#5 1180,2110 r90 top net-tie
NT404 "Net_Tie" "NET TIE"#4 2232.59,1390.87 r0 top net-tie
NT405 "Net_Tie" "NET TIE"#5 1180,2259 r90 top net-tie
NT1000 "Net_Tie" "NET TIE"#6 3616.97,2929.52 r270 bottom net-tie
NT1001 "Net_Tie" "NET TIE"#6 3615.97,3089.52 r90 bottom net-tie
PS400 "" "3717 TC2_2 DCM-50840P1" 2722.44,1667.32 r90 top
Q300 "SOT23_3" SOT23_3-F 951.38,372.05 r180 top
Q800 "SOT223" SOT223-F-PMT280ENEA-REFLOW 2040,2250 r0 top
Q801 "SOT523_3" SOT523-T 1681.89,2131.18 r180 top
Q1000 "SOT669" "PSMN6R9-100YSF SOT669 Reflow" 3643,2599.52 r270 bottom
Q1001 "SOT669" "PSMN6R9-100YSF SOT669 Reflow" 4046.44,2599.52 r270 bottom
R300 "0603" 0603-R-FLT 1069.49,372.05 r270 top
R301 "1206" 1206-R_L 1782.98,1833.26 r0 top
R302 "0603" 0603-R-FLT 997.91,3076.24 r90 top
R303 "0603" 0603-R-FLT 945.75,3076.24 r90 top
R304 "0603" 0603-R-FLT 1050.72,3077.72 r270 top
R305 "0603" 0603-R-FLT 864.5,3090.55 r0 top
R306 "0603" 0603-R-FLT 1851.13,2887.91 r270 top
R400 "1206" 1206-R_L 1512,1138.3 r180 top
R401 "1206" 1206-R-FLT 1302.44,1138.3 r180 top
R402 "2512" 2512-R_L 1180,2163 r90 top
R404 "2512" 2512-R_L 2211.25,966.77 r0 bottom
R405 "2512" 2512-R_L 2209.24,1142.65 r0 bottom
R800 "0603" 0603-R-FLT 1781.89,2312.18 r0 top
R801 "1206" 1206-R_L 1741.89,2226.18 r0 top
R802 "0603" 0603-R-FLT 1706.89,2041.18 r90 top
R803 "0603" 0603-R-FLT 1821.89,2151.1 r180 top
R900 "0805" 0805-R-FLT 3322.48,244.26 r180 top
R1000 "0603" 0603-R-FLT 3897.97,2673.4 r90 bottom
R1001 "4527" 4527-VISHAY 3617.97,3008.52 r90 bottom
R1002 "4527" 4527-VISHAY 4021.97,3008.52 r90 bottom
S300 "SW_GT11MSABE" SW_GT11MSABE 629.8,406 r180 top
TP200 "TEST_POINT" TP_030_RND_SMD#1 3932.98,1071.26 r90 bottom
TP201 "TEST_POINT" TP_030_RND_SMD#1 644.98,2468.26 r90 bottom
TP202 "TEST_POINT" TP_030_RND_SMD#1 -252.02,471.26 r90 bottom
TP203 "TEST_POINT" TP_030_RND_SMD#1 4025,275 r90 bottom
TP300 "TEST_POINT" TP_030_RND_SMD#1 1923.98,1839.74 r90 bottom
TP301 "TEST_POINT" TP_030_RND_SMD#1 1046.98,3093.26 r90 bottom
TP302 "TEST_POINT" TP_030_RND_SMD#1 2343.98,2866.26 r90 bottom
TP303 "TEST_POINT" TP_030_RND_SMD#1 1295.98,3193.26 r90 bottom
TP400 "TEST_POINT" TP_030_RND_SMD#1 3260.98,3145.26 r90 bottom
TP401 "TEST_POINT" TP_030_RND_SMD#1 1963.98,1950.26 r90 bottom
TP402 "TEST_POINT" TP_030_RND_SMD#1 1923.98,1494.85 r90 bottom
TP403 "TEST_POINT" TP_030_RND_SMD#1 1923.98,1425.96 r90 bottom
TP404 "TEST_POINT" TP_030_RND_SMD#1 1923.98,1701.94 r90 bottom
TP405 "TEST_POINT" TP_030_RND_SMD#2 1651.98,2293.2 r90 bottom
TP406 "TEST_POINT" TP_030_RND_SMD#1 1775.21,411.26 r90 bottom
TP407 "TEST_POINT" TP_030_RND_SMD#1 1974.98,134.26 r90 bottom
TP408 "TEST_POINT" TP_030_RND_SMD#1 1674.98,411.26 r90 bottom

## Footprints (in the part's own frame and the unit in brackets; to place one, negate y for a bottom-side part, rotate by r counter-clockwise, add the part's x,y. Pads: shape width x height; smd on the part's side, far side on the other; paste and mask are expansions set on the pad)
0603-C_L [mm] "0603-C_026_030_082 Least"
  rect 0.65x0.75 smd mask+0.05: 1(-0.713,0) 2(0.713,0)
  body extent -0.87,-0.48 0.87,0.48, height 0.01
0603-R-FLT [mm] "0603-R Filletless"
  rrect35% 0.55x0.8 smd mask+0.05: 1(-0.675,0) 2(0.675,0)
  body extent -0.9,-0.54 0.9,0.54, height 0.01
0805-R-FLT [mm] "0805-R Filletless"
  rrect30% 0.65x1.25 smd mask+0.05: 1(-0.825,0) 2(0.825,0)
  body extent -1.11,-0.73 1.11,0.73, height 0.01
1206-C-FLT [mm] "1206-C Filletless"
  rrect30% 0.85x1.6 smd mask+0.05: 1(-1.325,0) 2(1.325,0)
  body extent -1.72,-0.91 1.72,0.91, height 0.01
1206-C-GRM31CC72A475KE11 [mil] "Murata 1206 3.5x1.9x1.9"
  rrect30% 34.94x62.99 smd mask+1.97: 1(-52.5,0) 2(52.5,0)
  body extent -69,-37 69,37, height 0
1206-L_BLM31P [mil] "1206-L_037_062_146 BLM31P"
  rect 34.94x62.99 smd mask+1.97: 1(-52.5,0) 2(52.5,0)
  body extent -67,-35 67,35, height 0
1206-R-FLT [mm] "1206-R Filletless"
  rrect30% 0.85x1.6 smd mask+0.05: 1(-1.325,0) 2(1.325,0)
  body extent -1.71,-0.92 1.71,0.92, height 0
1206-R_L [mm] "1206-R_037_062_146 Least"
  rrect1% 0.95x1.6 smd mask+0.05: 1(-1.375,0) 2(1.375,0)
  body extent -1.72,-0.91 1.73,0.92, height 0
2512-R_L [mil] "2512-R_045_145_280_035"
  rrect1% 45x145 smd mask+1.97: 1(-117.5,0) 2(117.5,0)
  body extent -130,-67 130,67, height 0
2727 [mm] "Inductor Common Mode"
  rect 2x3 smd: 1(-2.65,0) 2(2.65,0)
  body extent -3.6,-3.5 3.6,3.5, height 0
"3717 TC2_2 DCM-50840P1" [mm] "3717 TC2_2 DCM PRODUCT OUTLINE"
  rect 1.23x3.47 smd mask-0.05: 1(-8.445,15.14) 5(8.445,15.14)
  rect 1.23x1.38 smd mask-0.05: 2(-8.445,11.35)
  rect 15.04x1.23 smd mask-0.05: 3(0,-18.135)
  rect 1.231x1.38 smd mask-0.05: 4(8.445,11.35)
  rect 1.245x1.23 smd mask-0.05: 6(6.13,18.135) 7(4.38,18.135) 8(2.63,18.135) 9(0.88,18.135) 10(-0.88,18.135) 11(-2.63,18.135) 12(-4.38,18.135) 13(-6.13,18.135)
  round 1.6 smd mask-0.05: 14(-7,-11) 14(-7,-9) 14(-7,-7) 14(-7,-5) 14(-7,-3) 14(-7,-1) 14(-7,1) 14(-7,3) 14(-7,5) 14(-7,7) 14(-7,9) 14(-7,-15) 14(-7,-13) 14(-6,11) 14(-5,7) 14(-5,9) 14(-5,13) 14(-5,15) 14(-5,-5) 14(-5,-3) 14(-5,-1) 14(-5,1) 14(-5,3) 14(-5,5) 14(-5,-15) 14(-5,-13) 14(-5,-11) 14(-5,-9) 14(-5,-7) 14(-4,11) 14(-3,15) 14(-3,9) 14(-3,13) 14(-3,3) 14(-3,5) 14(-3,7) 14(-3,-1) 14(-3,1) 14(-3,-7) 14(-3,-5) 14(-3,-3) 14(-3,-13) 14(-3,-11) 14(-3,-9) 14(-3,-15) 14(-2,11) 14(-1,15) 14(-1,13) 14(-1,9) 14(-1,5) 14(-1,7) 14(-1,3) 14(-1,-1) 14(-1,1) 14(-1,-3) 14(-1,-7) 14(-1,-5) 14(-1,-9) 14(-1,-13) 14(-1,-11) 14(-1,-15) 14(0,11) 14(1,15) 14(1,13) 14(1,9) 14(1,5) 14(1,7) 14(1,3) 14(1,-1) 14(1,1) 14(1,-3) 14(1,-7) 14(1,-5) 14(1,-9) 14(1,-13) 14(1,-11) 14(1,-15) 14(2,11) 14(3,15) 14(3,9) 14(3,13) 14(3,3) 14(3,5) 14(3,7) 14(3,-1) 14(3,1) 14(3,-7) 14(3,-5) 14(3,-3) 14(3,-13) 14(3,-11) 14(3,-9) 14(3,-15) 14(4,11) 14(5,7) 14(5,9) 14(5,13) 14(5,15) 14(5,-5) 14(5,-3) 14(5,-1) 14(5,1) 14(5,3) 14(5,5) 14(5,-15) 14(5,-13) 14(5,-11) 14(5,-9) 14(5,-7) 14(6,11) 14(7,-11) 14(7,-9) 14(7,-7) 14(7,-5) 14(7,-3) 14(7,-1) 14(7,1) 14(7,3) 14(7,5) 14(7,7) 14(7,9) 14(7,-15) 14(7,-13)
  body extent -8.67,-18.35 8.67,18.36, height 0
4527-VISHAY [mm] "Power Metal Strip® Resistors, Low Value (down to 0.001 ?), Surface Mount  WSR"
  rect 3.94x5.84 smd mask+0.05: 1(-4.575,0) 2(4.575,0)
  body extent -6.17,-3.55 6.19,3.55, height 0.83
C_ALEL10X12R7 [mm] "Aluminum Alectrolytic SMT Capacitor"
  rect 4x1.5 smd mask+0.05: 1(-3.5,0) 2(3.5,0)
  body extent -5.26,-5.23 5.24,5.27, height 10
CN1_MILLMAX_SM_RECEPTACLE [mil] "SM RECEPTACLE 8806-0-58-15-47-27-40-0"
  rect 95x69 smd mask+1.97: 1(0,0)
  body extent -60,-50 55,50, height 0
CN2_HARWIN-M20877XXXX [mil] "1x2 SMD pin header"
  rect 50x110 smd: 1(50,-57.5) 2(-50,57.5)
  body extent -100,-50 100,50, height 0
CN3_HARWIN-M20#1 [mm]
  rect 1x2.51 smd: 1(-2.54,1.637) 2(0,-1.655) 3(2.54,1.637)
  body extent -3.81,-2.47 3.81,2.61, height 0
CN3_HARWIN-M20#2 [mm]
  rect 1x2.51 smd: 1(-2.54,1.655) 2(0,-1.655) 3(2.54,1.655)
  body extent -3.81,-2.47 3.81,2.61, height 0
CN4_HARWIN-M20877XXXX [mm] "Header Assembly"
  rect 1x2.51 smd: 1(-3.808,1.66) 2(-1.268,-1.66) 3(1.272,1.66) 4(3.812,-1.66)
  body extent -5.09,-1.3 5.07,1.24, height 0
CN6_TE-2174507 [mm] "Micro USB Receptacle 2DIP Type B Flangeless"
  rect 0.4x1.35 smd mask+0.05: 1(-1.3,1.325) 2(-0.65,1.325) 3(0,1.325) 4(0.65,1.325) 5(1.3,1.325)
  rect 1.45x1.3 smd mask+0.05: 6(-3.425,-1.325) 6(3.425,-1.325)
  rect 1.6x1.4 smd mask+0.05: 6(-3.2,1.128) 6(3.2,1.128)
  rect 1.9x1.9 smd mask+0.05: 6(-1.225,-1.325) 6(1.225,-1.325)
  body extent -3.9,-3.43 3.9,1.56, height 0
CN8_DIGIKEY_95278 [mm] "Unshr Header DR SMT"
  rect 2.54x1.27 smd mask+0.05: 1(-2.78,3.81) 2(2.78,3.81) 3(-2.78,1.27) 4(2.78,1.27) 5(-2.78,-1.27) 6(2.78,-1.27) 7(-2.78,-3.81) 8(2.78,-3.81)
  body extent -3.5,-5.08 3.49,5.08, height 0
CN10_DIGIKEY_95278 [mm] "Unshr Header DR SMT"
  rect 2.54x1.27 smd mask+0.05: 1(-2.78,5.08) 2(2.78,5.08) 3(-2.78,2.54) 4(2.78,2.54) 5(-2.78,0) 6(2.78,0) 7(-2.78,-2.54) 8(2.78,-2.54) 9(-2.78,-5.08) 10(2.78,-5.08)
  body extent -3.64,-6.15 3.65,6.15, height 0
CN12_DIGIKEY_95278 [mm] "Unshr Header DR SMT"
  rect 2.54x1.27 smd mask+0.05: 1(-2.78,6.35) 2(2.68,6.35) 3(-2.78,3.81) 4(2.78,3.81) 5(-2.78,1.27) 6(2.78,1.27) 7(-2.78,-1.27) 8(2.78,-1.27) 9(-2.78,-3.81) 10(2.78,-3.81) 11(-2.78,-6.35) 12(2.78,-6.35)
  body extent -2.41,-7.62 2.41,7.62
F_NANO_456-XXA [mm] "NANO HIGH CURRENT 456 SERIES 12.1x 4.4  40 amp"
  rect 3.79x5.65 smd mask+0.05: 1(-4.755,0) 2(4.755,0)
  body extent -6.05,-2.25 6.05,2.25, height 4.5
F_NANO_456-XXA-XXA [mm] "FUSE NANO 456 SERIES"
  rect 3.25x3.43 smd mask+0.05: 1(-4.675,0) 2(4.675,0)
  body extent -5.05,-1.56 5.05,1.56, height 0
FIDUCIAL-040 [mm] "Round Fiducial 40 mill pad"
  round 1 smd mask+0.508: 1(0,0)
"HEAT SINK 40x40" [mil]
  silkscreen extent -787,-787 787,787, body extent -787,-787 787,787, height 197
"KFS2-M3 4.22"#1 [mm] "Non plated hole 4.22 with a 8.8 no route,no place keep out all lyrs"
  round 6.5 / inner round 0 / far side round 0 hole 4.35 unplated mask+2.235: 1(0,0)
"KFS2-M3 4.22"#2 [mm] "Non plated hole 4.22 with a 8.8 no route,no place keep out all lyrs"
  round 6.5 / inner round 0 / far side round 0 hole 4.35 unplated mask+2.261: 1(0,0)
"NET TIE"#1 [mil] "NET TIE"
  rect 20x11.81 on Mid2 mask-50: 1(-9,0) 2(9,0)
"NET TIE"#2 [mil] "NET TIE"
  rect 37x11.81 on Mid6 mask-50: 1(-20,0) 2(15,0)
"NET TIE"#3 [mil] "NET TIE"
  rect 13.78x11.81 on Mid2 mask+0: 1(-6.89,0)
  rect 15.75x11.81 on Mid2 mask+0: 2(6.89,0)
"NET TIE"#4 [mil] "NET TIE"
  rect 17x11.81 on Mid5 mask-50: 1(-9,0)
  rect 20x11.81 on Mid5 mask-50: 2(9,0)
"NET TIE"#5 [mil] "NET TIE"
  rect 13.78x11.81 on Mid2 mask+0: 1(-6.89,0)
  rect 15x11.81 on Mid2 mask+0: 2(6.89,0)
"NET TIE"#6 [mil] "NET TIE"
  rect 17x11.81 smd mask-50: 1(-6.89,0) 2(6.89,0)
"PSMN6R9-100YSF SOT669 Reflow" [mm] "SOT669 REFLOW soldering footprint information for LFPAK56 48226 & 51401"
  rect 0.6x0.9 on Bottom Paste mask+0.05: D(-0.55,-1.15) D(-0.55,0) D(-0.55,1.15) D(0.3,-1.15) D(0.3,0) D(0.3,1.15) D(1.15,-1.15) D(1.15,0) D(1.15,1.15)
  rect 3.2x4.2 smd paste-100 mask-100: D(0.5,0)
  rect 1.5x4.7 smd paste-100 mask-100: D(2.75,0)
  rect 0.9x0.6 on Bottom Paste mask+0.05: D(3,-1.905) D(3,-0.635) D(3,0.635) D(3,1.905)
  rect 1.15x0.7 smd mask+0.05: G(-2.725,-1.905) S(-2.725,-0.635) S(-2.725,0.635) S(-2.725,1.905)
  silkscreen extent -1.9,-2.4 1.8,2.41, body extent -3.05,-2.4 3.06,2.41, height 0
"RADSERT-10-737-491-001 MASK PLUGGED" [mil] "RADSERT-10-737-491-001 SUPER TWIST"
  round 30 hole 29.92 mask+2: 1(-206.42,-50.88) 1(-206.42,50.88) 1(-159.13,-140.98) 1(-159.13,140.98) 1(-75.39,-198.78) 1(-75.39,198.78) 1(25.63,-211.05) 1(25.63,211.05) 1(120.77,-174.96) 1(120.77,174.96) 1(188.25,-98.8) 1(188.25,98.8) 1(212.6,0)
  round 472.44 hole 261.81 mask-45.28: 1(0,0)
  body extent -157,-157 157,157, height 0
"SCOPE JACK" [mm] "SCOPE JACK MMCX-SM"
  round 1.295 smd: 1(0,0)
  rrect10% 0.75x0.75 smd: 2(-1.375,-1.375) 2(-1.375,1.375) 2(1.375,-1.375) 2(1.375,1.375)
  Top Layer region: 0.914,-0.889 0.801,-0.987 0.65,-1.092 0.65,-2.095 1.703,-2.095 1.806,-2.012 1.899,-1.918 1.992,-1.825 2.095,-1.703 2.095,-0.65 1.092,-0.65 1.013,-0.768
  Top Layer region: -0.914,-0.889 -0.801,-0.987 -0.65,-1.092 -0.65,-2.095 -1.703,-2.095 -1.806,-2.012 -1.899,-1.918 -1.992,-1.825 -2.095,-1.703 -2.095,-0.65 -1.092,-0.65 -1.013,-0.768
  Top Layer region: 0.914,0.889 0.801,0.987 0.65,1.092 0.65,2.095 1.703,2.095 1.806,2.012 1.899,1.918 1.992,1.825 2.095,1.703 2.095,0.65 1.092,0.65 1.013,0.768
  Top Layer region: -0.914,0.889 -0.801,0.987 -0.65,1.092 -0.65,2.095 -1.703,2.095 -1.806,2.012 -1.899,1.918 -1.992,1.825 -2.095,1.703 -2.095,0.65 -1.092,0.65 -1.013,0.768
  body extent -1.75,-1.75 1.75,1.75, height 5.3
SOD123-D-MMSZ4 [mm] "SOD-123; 2 Leads; Body 2.84x 1.8mm, (LxW)"
  rect 0.91x1.22 smd mask+0.05: A(1.635,0) C(-1.635,0)
  body extent -1.93,-0.9 1.93,0.9, height 0
SOD123_L [mm] "SOD-123; 2 Leads; Body 2.84x 1.8mm, (LxW)"
  rect 0.91x1.22 smd mask+0.05: A(1.635,0) C(-1.635,0)
  body extent -1.93,-0.9 1.93,0.9, height 0
SOD123F-NEXPERIA [mm] "SOD123F-NEXPERIA"
  rect 1.1x1.2 smd mask+0.05: A(1.4,0) C(-1.4,0)
  body extent -1.35,-0.85 1.35,0.85, height 0
SOD523-SDMIOU45 [mm] "SOD523-SDMIOU45"
  rect 0.6x0.8 smd mask+0.05: A(0.85,0) C(-0.85,0)
  body extent -0.85,-0.45 0.85,0.45, height 0
SOT23_3-F [mm] "SOT23_3-FET"
  rect 0.7x0.7 smd: D(1.088,0) G(-1.088,1) S(-1.088,-1)
  body extent -0.7,-1.5 0.7,1.5, height 0.1
SOT223-F-PMT280ENEA-REFLOW [mm] "SOT-223/SC-73; 4 Leads; Body 6.7 x 7.3 mm, inc. leads (LxW max)"
  rect 1.3x1.3 smd paste-0.05 mask+0.05: D(-3.05,0) G(-3.05,2.3) S(-3.05,-2.3)
  rect 1.3x3.6 smd paste-5 mask+0.05: D(3.05,0)
  body extent -3.5,-3.36 3.51,3.34, height 0
SOT353-D [mm] "SOT-353 2.20mm x 1.35mm Diode"
  rect 0.65x0.4 smd mask+0.05: A(-0.895,0) C1(-0.895,0.65) C2(-0.895,-0.65) C3(0.896,-0.65) C4(0.896,0.65)
  body extent -0.67,-1.12 0.67,1.12, height 1.1
SOT523-T [mm] "SOT523, 3-Leads, Body1.7x.85mm, Transistor"
  rect 0.51x0.4 smd mask+0.05: B(-0.65,0.5) C(0.65,0) E(-0.65,-0.5)
  body extent -0.42,-0.85 0.42,0.85, height 0
SW_GT11MSABE [mil] "SWITCH, SMD, 3POS SPDT"
  rect 80x30 smd mask+1.97: 0(157.48,-100) 0(157.48,100) 1(-157.48,100) 2(-157.48,0) 3(-157.48,-100)
  body extent -117,-138 320,138
TP_030_RND_SMD#1 [mil] "TESTPOINT_030_ROUND_SMD"
  round 40 smd mask+1.97: 1(0,0)
  body extent -17,-17 17,17, height 20
TP_030_RND_SMD#2 [mil] "TESTPOINT_030_ROUND_SMD"
  round 30 smd mask+1.97: 1(0,0)
  body extent -17,-17 17,17

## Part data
C300: "Capacitor", TOLERANCE=10, VALUE_MAX=0.011, VALUE_MIN=0.009, VALUE_NOM=0.01uF, VOLTAGE_RATING_NOM=100V
C301: library part 29400-104, "Capacitor", TOLERANCE=10, VALUE_MAX=0.11, VALUE_MIN=0.09, VALUE_NOM=0.1uF, VOLTAGE_RATING_NOM=50V
C400 C401 C402 C403: library part 47650-566, "Polarized Capacitor", TOLERANCE=20, VALUE_MAX=67.2, VALUE_MIN=44.8, VALUE_NOM=56uF, VOLT_COEF_A3=-1, VOLTAGE_RATING_NOM=80V
C404 C405 C406 C407 C416 C417: library part 37238-475, "Capacitor", TOLERANCE=10, VALUE_MAX=5.17, VALUE_MIN=4.23, VALUE_NOM=4.7u, VOLTAGE_RATING_NOM=100V
C408 C409 C410 C411 C412 C413 C414 C415 C418 C419 C420 C421: library part 42177-226, "Capacitor", TOLERANCE=10, VALUE_MAX=24.2, VALUE_MIN=19.8, VALUE_NOM=22u, VOLTAGE_RATING_NOM=25V
D300: library part 39193-5V6, "SOT353 BZA800AVL", CONTINUOUS_REVERSE_VOLTAGE=?, OPER_TEMP_HIGH=150, OPER_TEMP_LOW=-65, PEAK_GATE_POWER=300, REVERSE_CURRENT=0.2, ZENER_TEST_CURRENT=1, ZENER_VOLTAGE_MAX=5.88, ZENER_VOLTAGE_MIN=5.32, ZENER_VOLTAGE_NOM=5.6
D301: library part 49595, "Schottky Diode", CONTINUOUS_REVERSE_VOLTAGE=?
D302: library part 50007-5V1, "Zener Diode", ZENER_VOLTAGE_MAX=5.355, ZENER_VOLTAGE_MIN=4.845, ZENER_VOLTAGE_NOM=5.1V
D800: library part 28968-4R7, "Zener Diode", OPER_TEMP_HIGH=150, OPER_TEMP_LOW=-55, PEAK_GATE_POWER=500, REVERSE_CURRENT=10, TOLERANCE=5, ZENER_TEST_CURRENT=0.05, ZENER_VOLTAGE_MAX=4.935, ZENER_VOLTAGE_MIN=4.465, ZENER_VOLTAGE_NOM=4v7
D1000 D1001: library part 28432-100, "Default Diode", CONTINUOUS_REVERSE_VOLTAGE=10V, OPER_TEMP_HIGH=150, OPER_TEMP_LOW=-55, PEAK_GATE_POWER=500, REVERSE_CURRENT=1, TOLERANCE=5, ZENER_TEST_CURRENT=0.05, ZENER_VOLTAGE_MAX=10.5, ZENER_VOLTAGE_MIN=9.5, ZENER_VOLTAGE_NOM=10
F400: library part 46433, "Fuse", COLD_RESISTANCE=0.0013, CURRENT_RATING_NOM=30, INTERRUPTING_CURRENT_RATING=1000, Package_Type="NANO 456", VALUE_NOM=30A, VOLTAGE_DROP=69.9, VOLTAGE_RATING_NOM=125
F401: library part 37688, "Fuse", CURRENT_RATING_NOM=40, INTERRUPTING_CURRENT_RATING=600, Manufacturer="LITTLE FUSE", VALUE_NOM=40A, VOLTAGE_DROP=55, VOLTAGE_RATING_NOM=60
FID01 FID02 FID03 FID04 FID05 FID06: "Fiducial"
HS400: library part "Heat Sink WITH GND", "Heat sink with GND", Package_Type=PKG_TYPE, VALUE_NOM=Value
J200 J201 J202 J203: library part HOLE, "Plated Hole/Non Plated Thru Hole"
J300 J303 J904 J905 J906 J907 J1000 J1001: library part 48547, "BNC Elbow Connector 2 Pins", CURRENT_RATING_NOM=0, VALUE_NOM=Value
J301: library part 42884, "CONNECTOR 4 PIN", CURRENT_RATING_NOM=-1, VALUE_NOM=Value
J302: library part 51948, "2 Pin Connector", CURRENT_RATING_NOM=3, Package_Type=CN2_HARWIN-M20, VALUE_NOM=Value, VOLTAGE_RATING_NOM=-1
J304: "CONN-6PIN-FEMALE", CURRENT_RATING_NOM=1, MANUF_ITEM_ID=2174507-2, Manufacturer=DIGI-KEY, VOLTAGE_RATING_NOM=5
J305 J900 J902 J903: library part 43305, "3 PIN CONNECTOR", CURRENT_RATING_NOM=3, VALUE_NOM=Value, VOLTAGE_RATING_NOM=750
J400 J401: "1 Pin Connector", CURRENT_RATING_NOM=1, VALUE_NOM=Value, VOLTAGE_RATING_NOM=100
J402 J403: library part 48687, "1 Pin Connector", CURRENT_RATING_NOM=4.5, MANUF_ITEM_ID=8806-0-58-15-47-27-40-0, Manufacturer=Mill-Max, VALUE_NOM=Value, VOLTAGE_RATING_NOM=-1
J800: library part 42829, "Header, 5-Pin, Dual row", CURRENT_RATING_NOM=-1, VALUE_NOM=Value
J901: library part 48899, "Header, 6-Pin, Dual row", CURRENT_RATING_NOM=3, VALUE_NOM=Value, VOLTAGE_RATING_NOM=1500
J1002: library part 49756, "CONNECTOR 8 PIN", CURRENT_RATING_NOM=0, VALUE_NOM=Value
L400: library part 29187-33R0, "Inductor", IRMS_HEATING_CURRENT_40DEGC=-1, MSL_RATING=6, OPER_TEMP_HIGH=125, OPER_TEMP_LOW=-55, TOLERANCE=25, VALUE_MAX=0.065, VALUE_MIN=0.039, VALUE_NOM=0.052
L401: library part 46244-72N, "Inductor", IRMS_HEATING_CURRENT_40DEGC=-1, ISAT_SATURATION_CURRENT=58, MSL_RATING=6, OPER_TEMP_HIGH=125, OPER_TEMP_LOW=-40, TOLERANCE=20, VALUE_MAX=0.0864, VALUE_MIN=0.0576, VALUE_NOM=72n, VALUE_TEST_FREQ=100
PS400: library part "3717 DCM TC2_2 DCM-50840P1", "3717 DCM TC2_2 PRODUCT OUTLINE"
Q300: library part 04884, "N-Channel Mosfet", CISS_INPUT_CAPACITANCE=-1, OPER_TEMP_HIGH=150, OPER_TEMP_LOW=-55, Part Number=?, PD_POWER_DISSIPATION_MAX=0.3, VALUE_NOM=Value, VDS_DRAIN_SOURCE_VOLTAGE=60V
Q800: "NMOS TRENCH MOSFET", VDS_DRAIN_SOURCE_VOLTAGE=?
Q801: library part 28595, "NPN-Transistor", VDS_DRAIN_SOURCE_VOLTAGE=?
Q1000 Q1001: library part 48226, "N-Channel Mosfet", CISS_INPUT_CAPACITANCE=6721, COSS_OUTPUT_CAPACITANCE=2390, ID_CONTINUOUS_DRAIN_CURRENT=300, OPER_TEMP_HIGH=175, OPER_TEMP_LOW=-55, Part Number=?, PD_POWER_DISSIPATION_MAX=238, RG_GATE_RESISTANCE_TYP=1.2, VALUE_NOM=Value, VDS_DRAIN_SOURCE_VOLTAGE=25V, VGS_GATE_VOLTAGE_MAX=20
R300: library part 15462-1002, "Resistor", POWER_RATING_NOM=0.1, TEMPERATURE_COEFFICIENT=100, TOLERANCE=1, VALUE_MAX=10.1, VALUE_MIN=9.9, VALUE_NOM=10k
R301: library part 02445-00R0, "Resistor", POWER_RATING_NOM=0.25, TOLERANCE=5, VALUE_MAX=0
R302 R303: library part 15462-2051, "Resistor", POWER_RATING_NOM=0.1, TEMPERATURE_COEFFICIENT=100, TOLERANCE=1, VALUE_MAX=2.0705, VALUE_MIN=2.0295, VALUE_NOM=2.05k
R304 R306: library part 15462-2000, "Resistor", OPER_TEMP_HIGH=155, OPER_TEMP_LOW=-55, POWER_RATING_NOM=0.125, TEMPERATURE_COEFFICIENT=100, TOLERANCE=1, VALUE_MAX=202, VALUE_MIN=198, VALUE_NOM=200
R305: "Resistor", POWER_RATING_NOM=0.1, TEMPERATURE_COEFFICIENT=100, TOLERANCE=1, VALUE_MAX=101, VALUE_MIN=99, VALUE_NOM=100k
R400: library part 02445-00R0, "Resistor", POWER_RATING_NOM=0.25, TOLERANCE=5, VALUE_MAX=0, VALUE_NOM="0 OHM"
R401: library part 03202-0R51, "Resistor", POWER_RATING_NOM=0.25, TOLERANCE=5, VALUE_MAX=0.5355, VALUE_MIN=0.4845, VALUE_NOM=0R51
R402: library part 47437-47L0, "Resistor", OPER_TEMP_HIGH=125, OPER_TEMP_LOW=-55, POWER_RATING_NOM=1, TEMPERATURE_COEFFICIENT=100, TOLERANCE=5, VALUE_MAX=49.35, VALUE_MIN=44.65, VALUE_NOM=47m
R404 R405: library part 35962-100L, "Resistor", OPER_TEMP_HIGH=170, OPER_TEMP_LOW=-65, POWER_RATING_NOM=1, TEMPERATURE_COEFFICIENT=75, VALUE_MAX=101, VALUE_MIN=99, VALUE_NOM=100
R800: library part 15462-1003, "Resistor", OPER_TEMP_HIGH=155, OPER_TEMP_LOW=-55, POWER_RATING_NOM=0.1, TEMPERATURE_COEFFICIENT=100, TOLERANCE=1, VALUE_MAX=101, VALUE_MIN=99, VALUE_NOM=100k
R801: library part 32413-4321, "Resistor", OPER_TEMP_HIGH=155, OPER_TEMP_LOW=-55, POWER_RATING_NOM=0.25, TEMPERATURE_COEFFICIENT=100, TOLERANCE=1, VALUE_MAX=4.3632, VALUE_MIN=4.2768, VALUE_NOM=4.32k
R802: library part 15462-1403, "Resistor", OPER_TEMP_HIGH=155, OPER_TEMP_LOW=-55, POWER_RATING_NOM=0.1, TEMPERATURE_COEFFICIENT=100, TOLERANCE=1, VALUE_MAX=141.4, VALUE_MIN=138.6, VALUE_NOM=140k
R803: library part 15462-4320, "Resistor", OPER_TEMP_HIGH=155, OPER_TEMP_LOW=-55, POWER_RATING_NOM=0.125, TEMPERATURE_COEFFICIENT=100, TOLERANCE=1, VALUE_MAX=436.32, VALUE_MIN=427.68, VALUE_NOM=432
R900: "Resistor", OPER_TEMP_HIGH=155, OPER_TEMP_LOW=-55, POWER_RATING_NOM=0.25, TEMPERATURE_COEFFICIENT=100, TOLERANCE=1, VALUE_MAX=50.399, VALUE_MIN=49.401, VALUE_NOM=49.9
R1000: library part 15462-1002, "Resistor", OPER_TEMP_HIGH=155, OPER_TEMP_LOW=55, POWER_RATING_NOM=0.1, TEMPERATURE_COEFFICIENT=100, TOLERANCE=1, VALUE_MAX=10.1, VALUE_MIN=9.9, VALUE_NOM=10kΩ
R1001 R1002: library part 50628-R070, "Resistor", POWER_RATING_NOM=5, TOLERANCE=1, VALUE_MAX=70.7, VALUE_MIN=69.3, VALUE_NOM=70
S300: library part 40538, "GT Series Sealed UltraminiatureToggle Switch", CURRENT_RATING_NOM=0.4, MSL_RATING=6, VALUE_NOM=Value
TP200 TP201 TP202 TP203 TP300 TP301 TP302 TP303 TP400 TP401 TP402 TP403 TP404 TP405 TP406 TP407 TP408: "Testpoint Round"

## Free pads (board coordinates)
  round 0 hole 150 unplated mask+78: 1(-224.41,70.87) 1(-224.41,3271.65) 1(4476.38,70.87) 1(4476.38,3271.65)

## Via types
v1: diameter 20, hole 10, Top Layer to Bottom Layer, tented both sides, 886 vias
v2: diameter 15/22/22/22/22/22/22/22 (per signal layer), hole 10, Top Layer to Bottom Layer, tented both sides, 414 vias

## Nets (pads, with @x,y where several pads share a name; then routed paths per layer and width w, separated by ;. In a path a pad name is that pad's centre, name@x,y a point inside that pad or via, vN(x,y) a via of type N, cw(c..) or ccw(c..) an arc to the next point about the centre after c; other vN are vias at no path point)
ADDR: PS400.9 R301.2 TP404.1 | length 282.8
  Top Layer w8: R301.2@1837.12,1833.26 1888.74,1833.26 1921,1801 1921,1745 1964.74,1701.26 PS400.9@1990.18,1701.26 ; PS400.9@2007.18,1701.26 2008.16,1702.24 PS400.9@2008.46,1701.94
  Bottom Layer w8: TP404.1@1923.98,1701.94 v1(1964.46,1701.94)
EAO: J901.1 J906.1 PS400.6 TP401.1 | length 2441.1
  Top Layer w8: v1(1964.46,1908.63) 2006.61,1908.63 PS400.6@2007.98,1907.26 ; v1(2186.7,65) J906.1@2290.98,65
  L3 w8: v1(2059.21,452.28) 2059.21,409.79 2141,328 2141,110.7 v1(2186.7,65)
  L6 w8: v1(1964.46,1908.63) 1803,1747.17 1803,450.66 1837.4,416.26 2023.18,416.26 v1(2059.21,452.28)
  Bottom Layer w8: TP401.1@1963.98,1950.26 1963.98,1909.11 v1(1964.46,1908.63) v1@1964.09,1908.26
EN: J302.1 J303.1 J901.5 PS400.7 R802.1 TP300.1 | length 3161.3
  Top Layer w8: J302.1@1254,260.63 1297.35,303.97 ; v1@1297.35,336 J303.1@1297.35,479.57 ; v1(1706.98,1983.2) R802.1@1706.98,2014.51 ; v1(1964.46,1839.74) 2008.51,1839.74 PS400.7@2009.98,1838.26
  Top Layer w20: 1297.35,303.97 v1(1297.35,335.25)
  L2 w20: v1(1251.68,335.25) v1(1274.51,335.25) v1(1297.35,335.25)
  L3 w8: v1@1302.35,336.29 1744.25,336.29 v1@1859.21,451.24
  L3 w20: v1(1251.68,335.25) v1(1274.51,335.25) v1(1297.35,335.25)
  L4 w20: v1(1251.68,335.25) v1(1274.51,335.25) v1(1297.35,335.25)
  L5 w20: v1(1251.68,335.25) v1(1274.51,335.25) v1(1297.35,335.25)
  L6 w8: v1(1706.98,1983.2) 1960.05,1983.2 2002.98,1940.26 2002.98,1878.26 v1(1964.46,1839.74) 1832.98,1708.26 1832.98,478.51 v1(1859.21,452.28)
  L6 w20: v1(1251.68,335.25) v1(1274.51,335.25) v1(1297.35,335.25)
  L7 w20: v1(1251.68,335.25) v1(1274.51,335.25) v1(1297.35,335.25)
  Bottom Layer w8: TP300.1@1923.98,1839.74 v1(1964.46,1839.74)
  Bottom Layer w20: v1(1251.68,335.25) v1(1274.51,335.25) v1(1297.35,335.25)
EN_EXT: J301.2 J302.2 Q300.D S300.2 | length 4864.6
  Top Layer w8: S300.2@787.28,406 v1(848.28,406) 882.23,372.05 Q300.D@908.56,372.05 ; v1(1303,95) 1349,95 J302.2@1349,117.5
  L2 w20: v1(1303,72.17) v1(1303,95) v1(1303,117.83) ; v1(1473.15,3234.26) v1(1495.98,3234.26) v1(1518.82,3234.26)
  L3 w20: v1(1303,72.17) v1(1303,95) v1(1303,117.83) ; v1(1473.15,3234.26) v1(1495.98,3234.26) v1(1518.82,3234.26)
  L4 w20: v1(1303,72.17) v1(1303,95) v1(1303,117.83) ; v1(1473.15,3234.26) v1(1495.98,3234.26) v1(1518.82,3234.26)
  L5 w20: v1(1303,72.17) v1(1303,95) v1(1303,117.83) ; v1(1473.15,3234.26) v1(1495.98,3234.26) v1(1518.82,3234.26)
  L6 w8: v1(848.28,406) 1136.44,117.83 v1(1303,117.83) 1399,117.83 1490,208.83 1490,474 1731,715 1731,1880.24 1495.98,2115.26 v1(1495.98,3234.26)
  L6 w20: v1(1303,72.17) v1(1303,95) v1(1303,117.83) ; v1(1473.15,3234.26) v1(1495.98,3234.26) v1(1518.82,3234.26)
  L7 w20: v1(1303,72.17) v1(1303,95) v1(1303,117.83) ; v1(1473.15,3234.26) v1(1495.98,3234.26) v1(1518.82,3234.26)
  Bottom Layer w20: v1(1303,72.17) v1(1303,95) v1(1303,117.83) ; v1(1473.15,3234.26) v1(1495.98,3234.26) v1(1518.82,3234.26)
EN_EXT*: J300.1 Q300.G R300.2 | length 657.5
  Top Layer w8: J300.1@630,65 838.73,65 1069.49,295.76 R300.2@1069.49,345.47 ; Q300.G@994.19,332.68 Q300.G@1000.78,339.26 ; Q300.G@1001.08,339.57 Q300.G@1000.78,339.26 ; R300.2@1063.58,339.57 1063.28,339.26 Q300.G@1000.78,339.26
FLT*: J901.3 J907.1 PS400.10 TP400.1 | length 5058.1
  Top Layer w8: v1(1964.46,1632.65) 1965.86,1631.26 PS400.10@2008.98,1631.26 ; v1(2686.7,65) J907.1@2790.98,65
  L3 w8: v1(1959.21,452.28) 2111,300.49 2111,62 2142,31 2207,31 2241,65 v1(2686.7,65) ; v1(1964.46,1632.65) 1875.46,1721.65 1875.46,2192.74 2041.98,2359.26 2041.98,2700.26 2120.98,2779.26 2766.26,2779.26 3091.26,3104.26 v1(3260.98,3104.26)
  L6 w8: v1(1959.21,452.28) 1875.21,536.28 1875.21,1525.17 1964.46,1614.43 v1(1964.46,1632.65)
  Bottom Layer w8: v1(3260.98,3104.26) TP400.1@3260.98,3145.26
I_SENSE_HI: J1001.1 J1002.1 J1002.3 NT1000.1 | length 751.6
  Top Layer w8: J1001.1@3341.97,3247.52 3341.97,2950.97 J1002.1@3390.97,2901.97 v1(3390.97,2833.52)
  L3 w8: v1(3390.97,2833.52) 3570.52,2833.52 3617,2880 v1@3617,2952
  other v1: 3617,2953
I_SENSE_LO: J1002.2 NT1001.1 | length 593.2
  Top Layer w8: J1002.2@3390.97,2683.07 v1(3390.97,2751.52)
  L3 w8: v1(3390.97,2751.52) 3444.45,2805 3584,2805 3655,2876 3655,2965 3616,3004 v1(3616,3067) v1@3616,3069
